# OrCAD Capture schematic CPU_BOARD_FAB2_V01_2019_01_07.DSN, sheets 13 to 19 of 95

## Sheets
13 054 COM-E_TYPE7_AB_2: size B
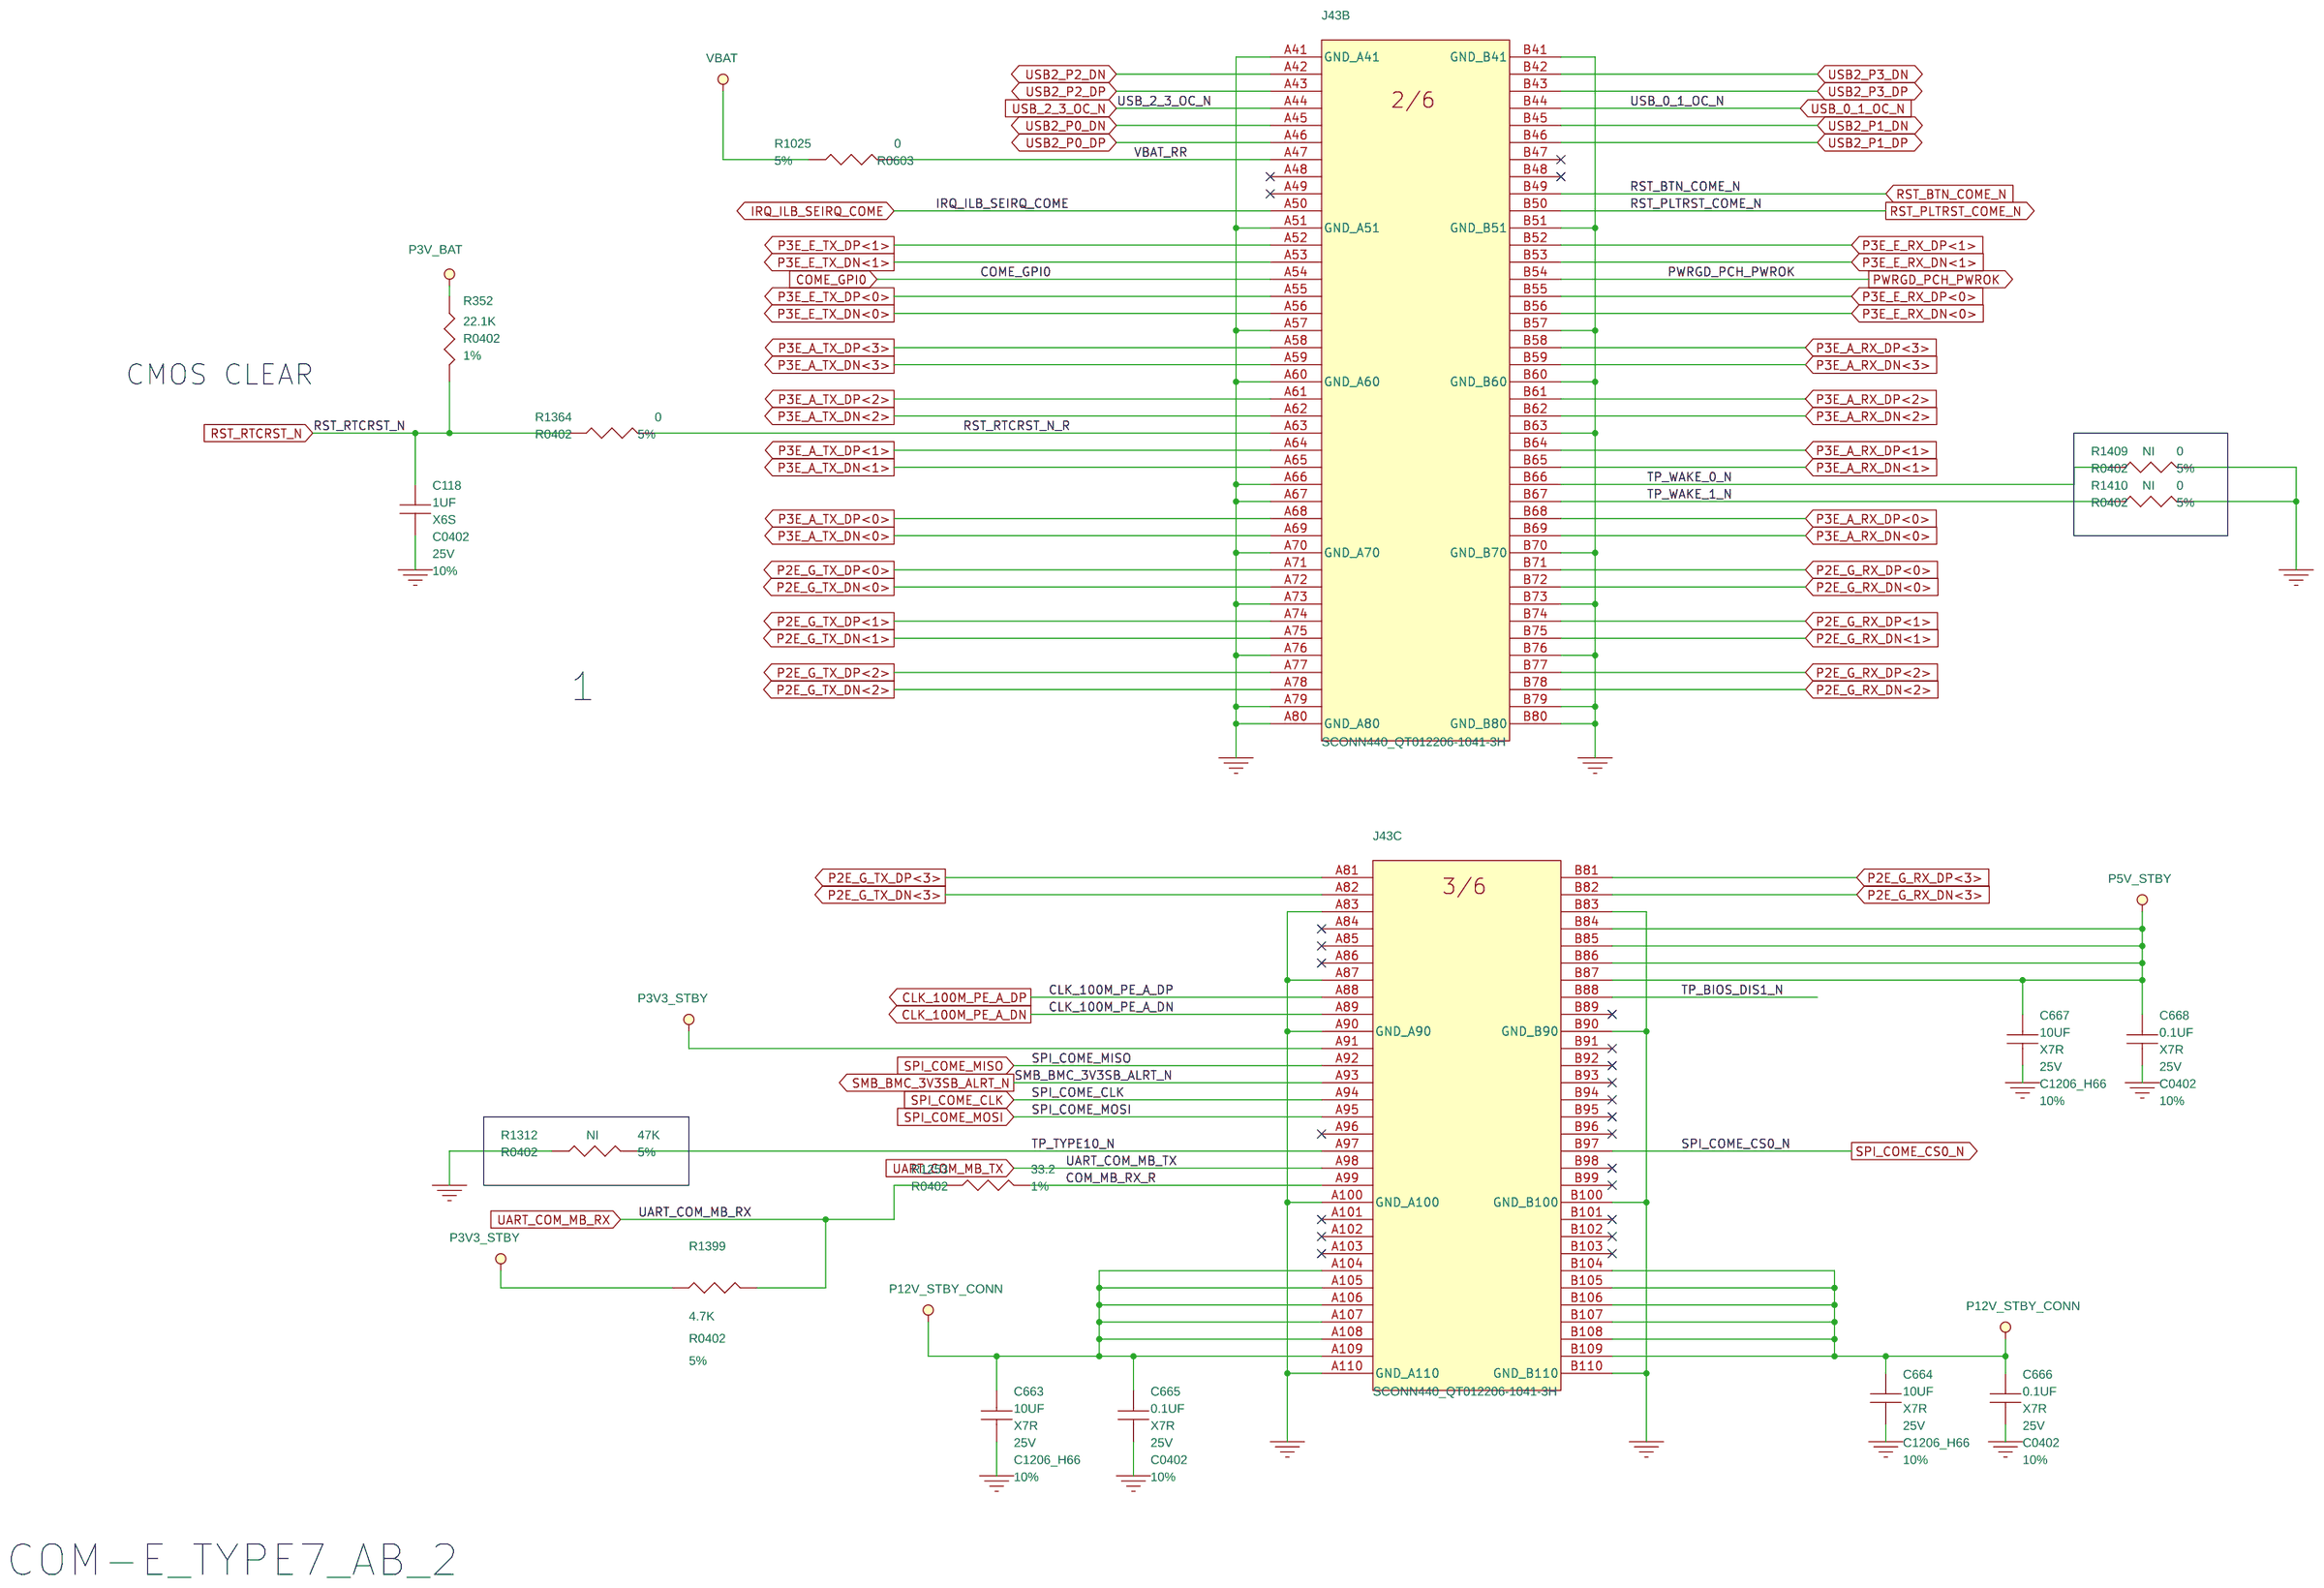
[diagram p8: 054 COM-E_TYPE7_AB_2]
14 052 CPLD_2: size B
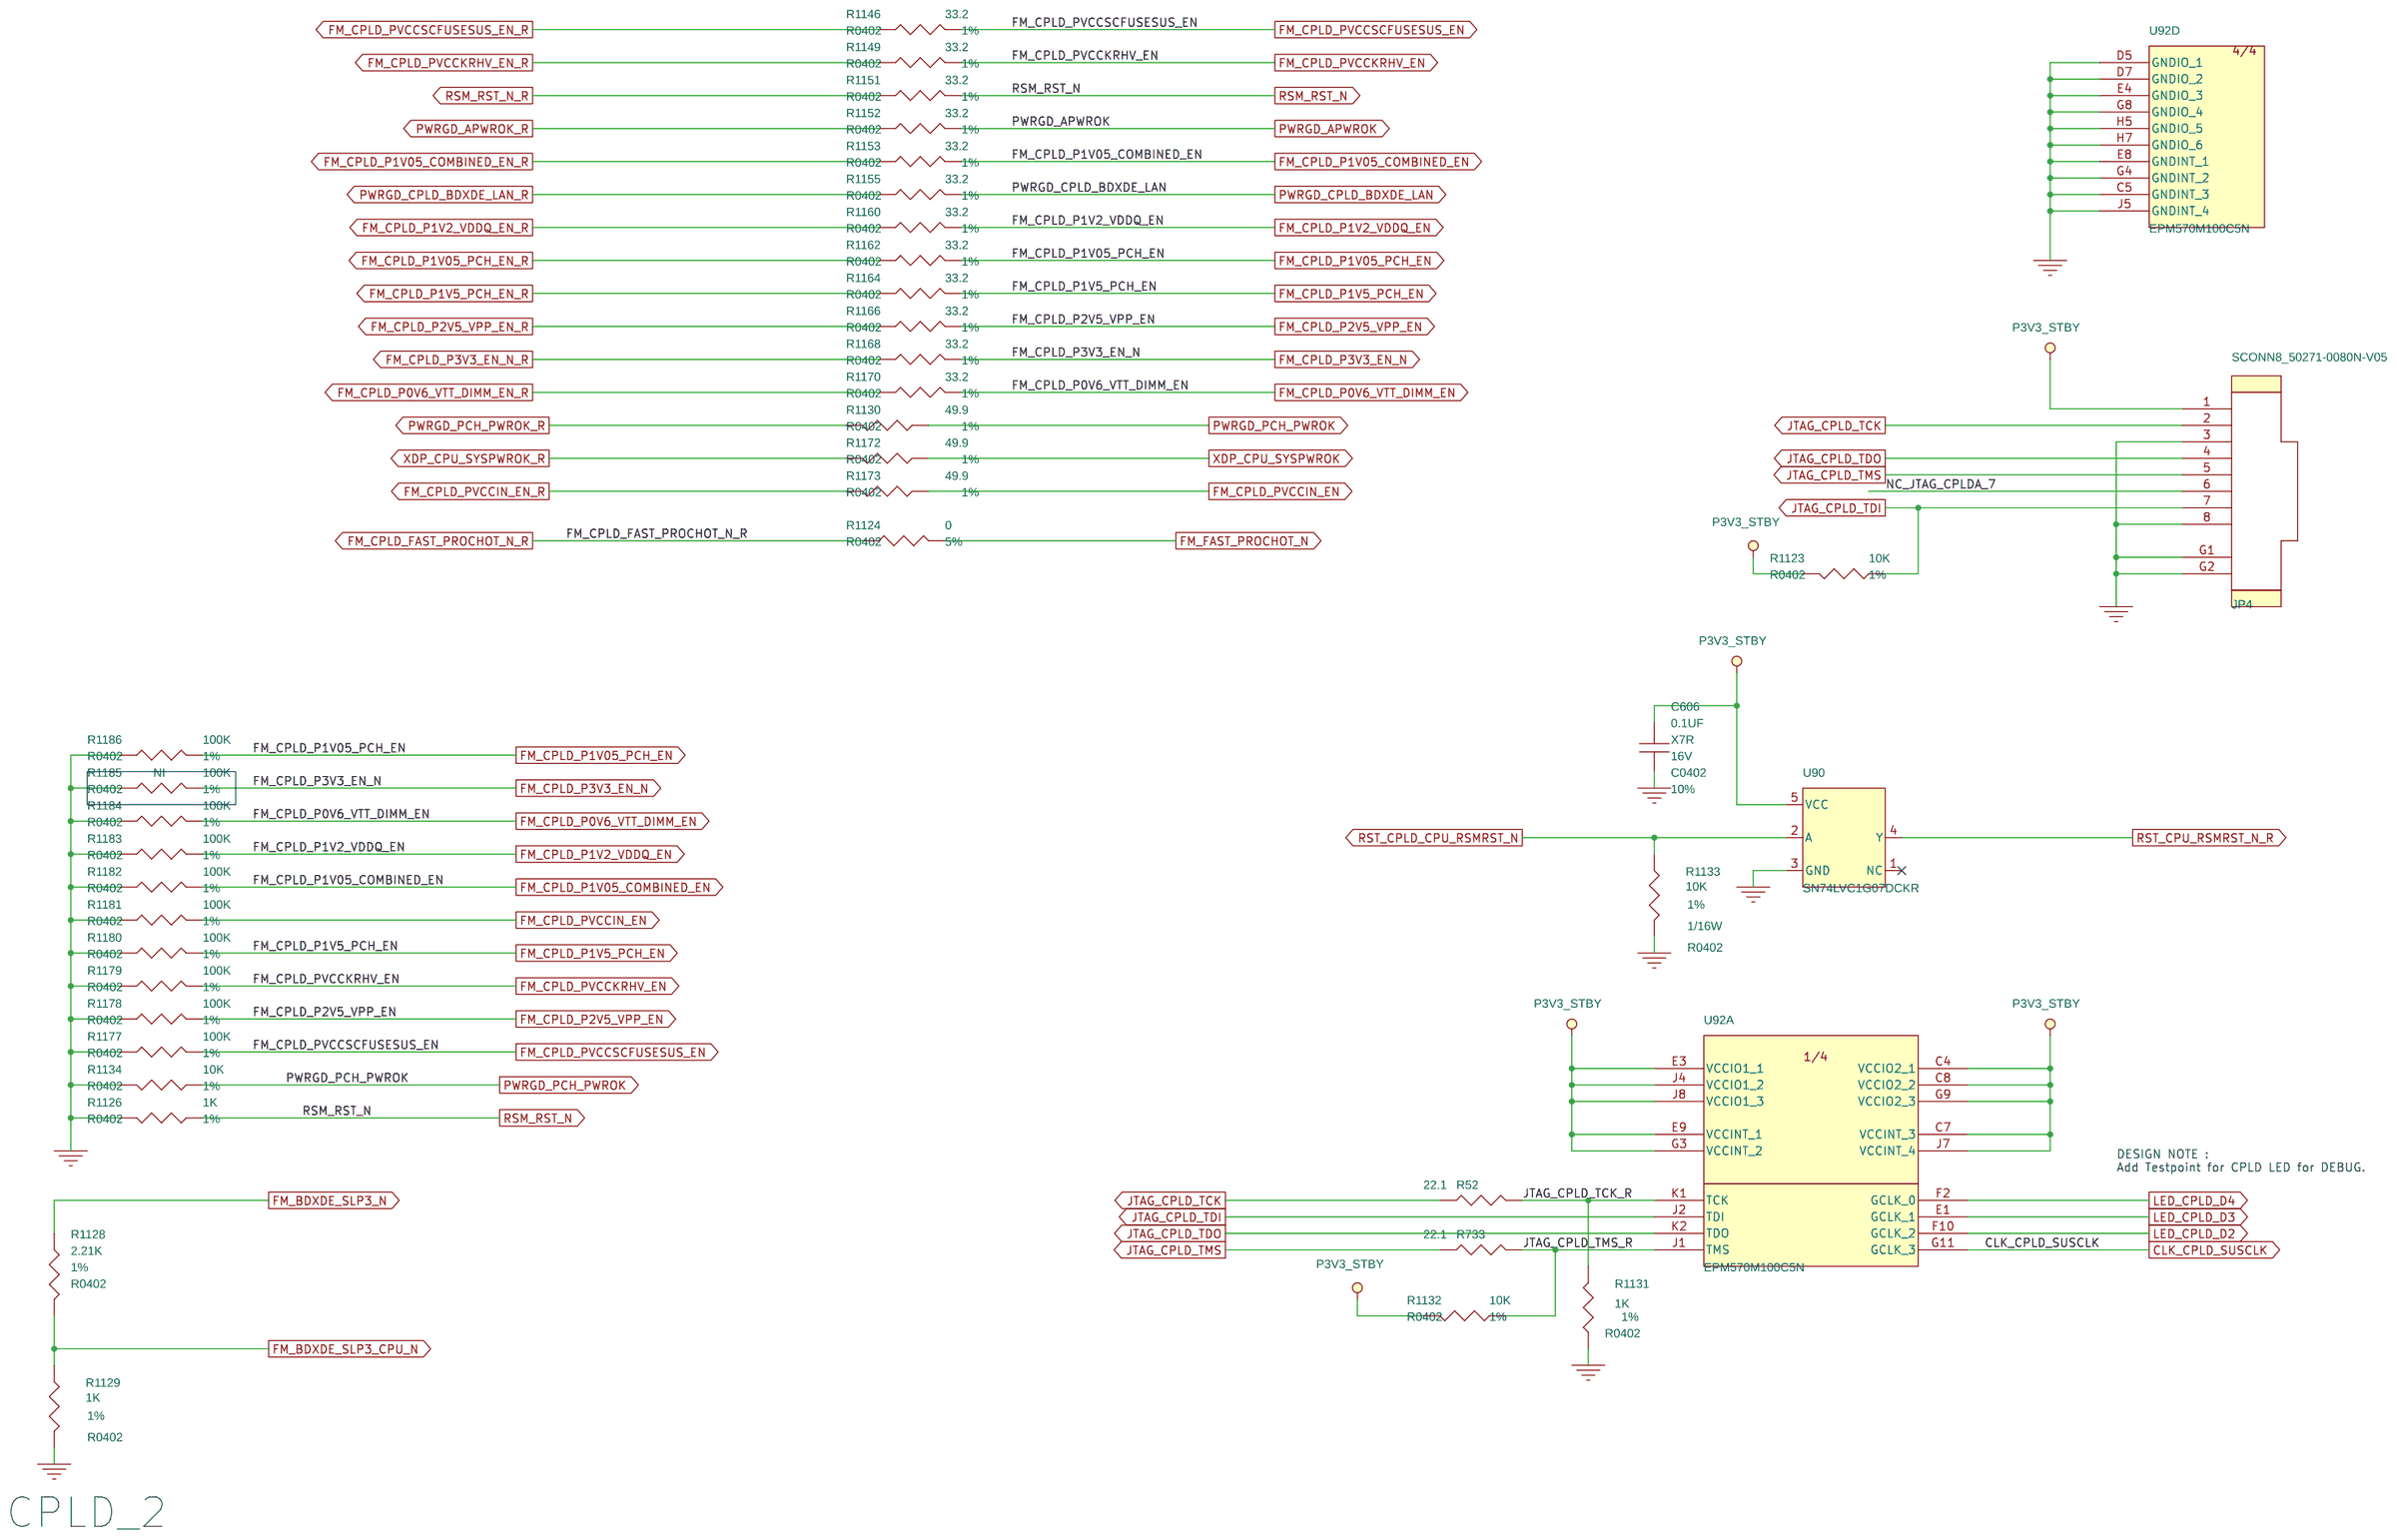
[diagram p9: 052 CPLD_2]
15 046 DDR4 SODIMM CHA_2: size B
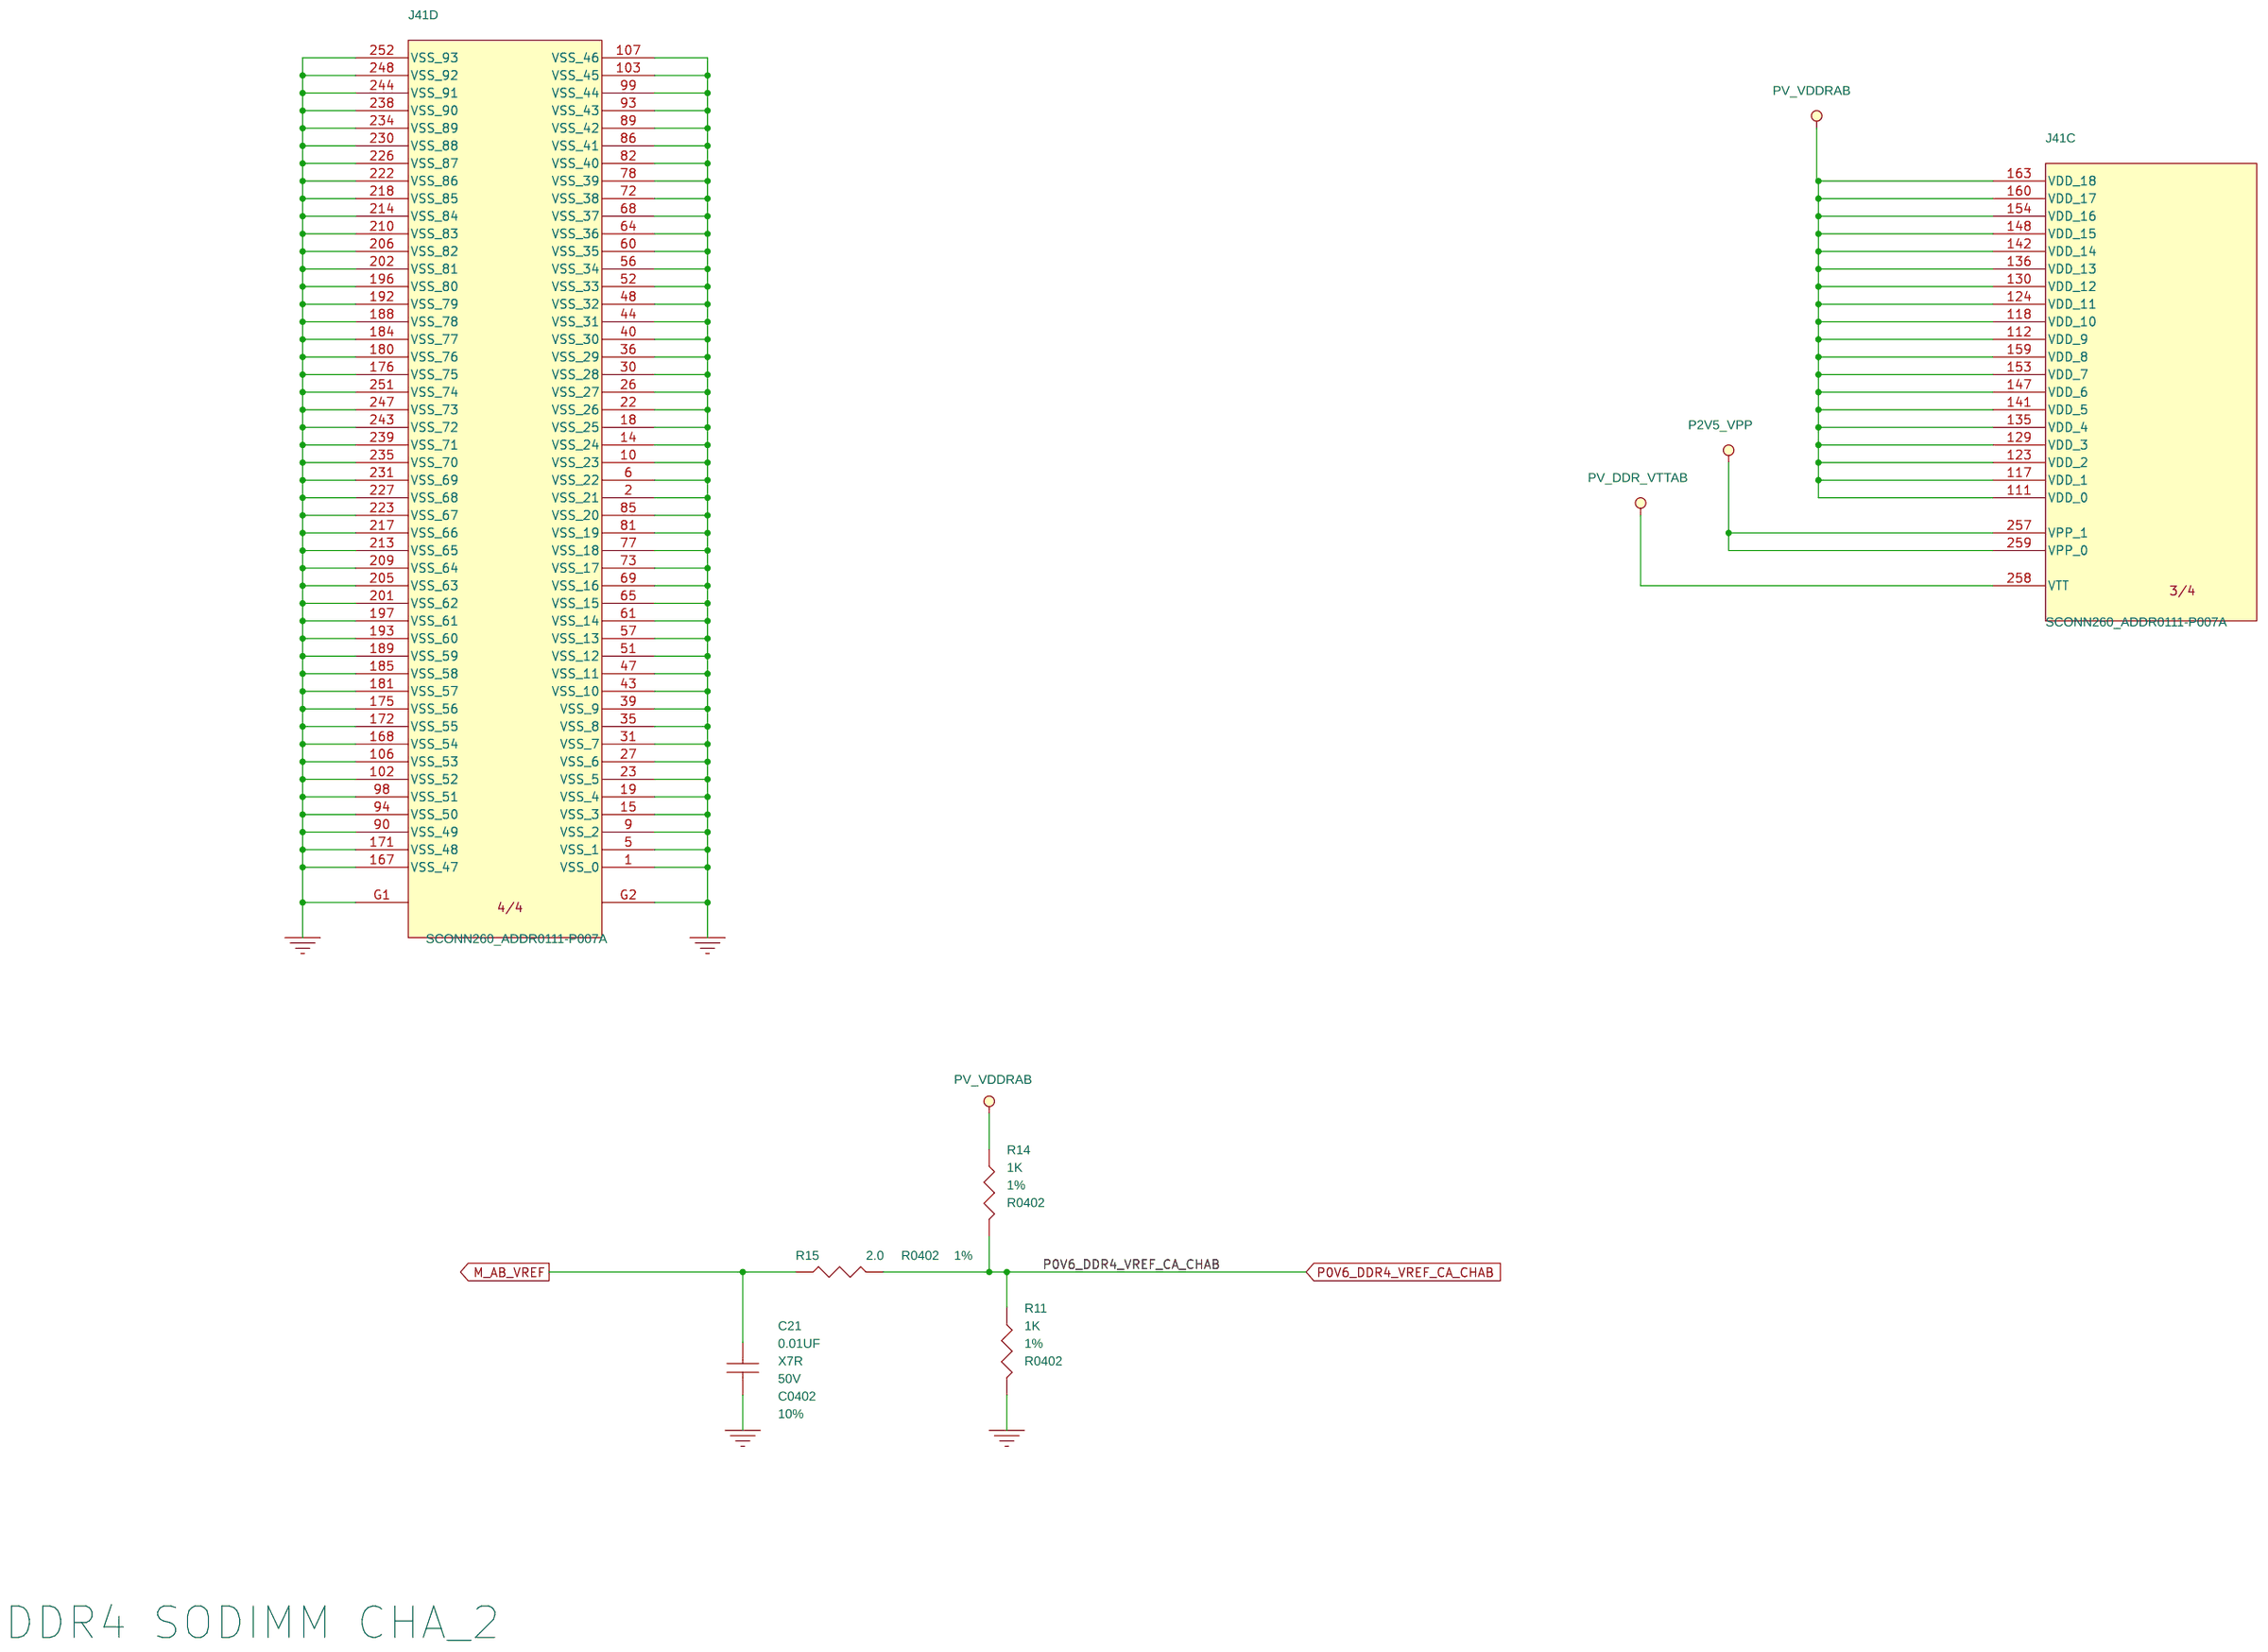
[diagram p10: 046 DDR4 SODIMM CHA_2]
16 037 CPU XDP_2: size B
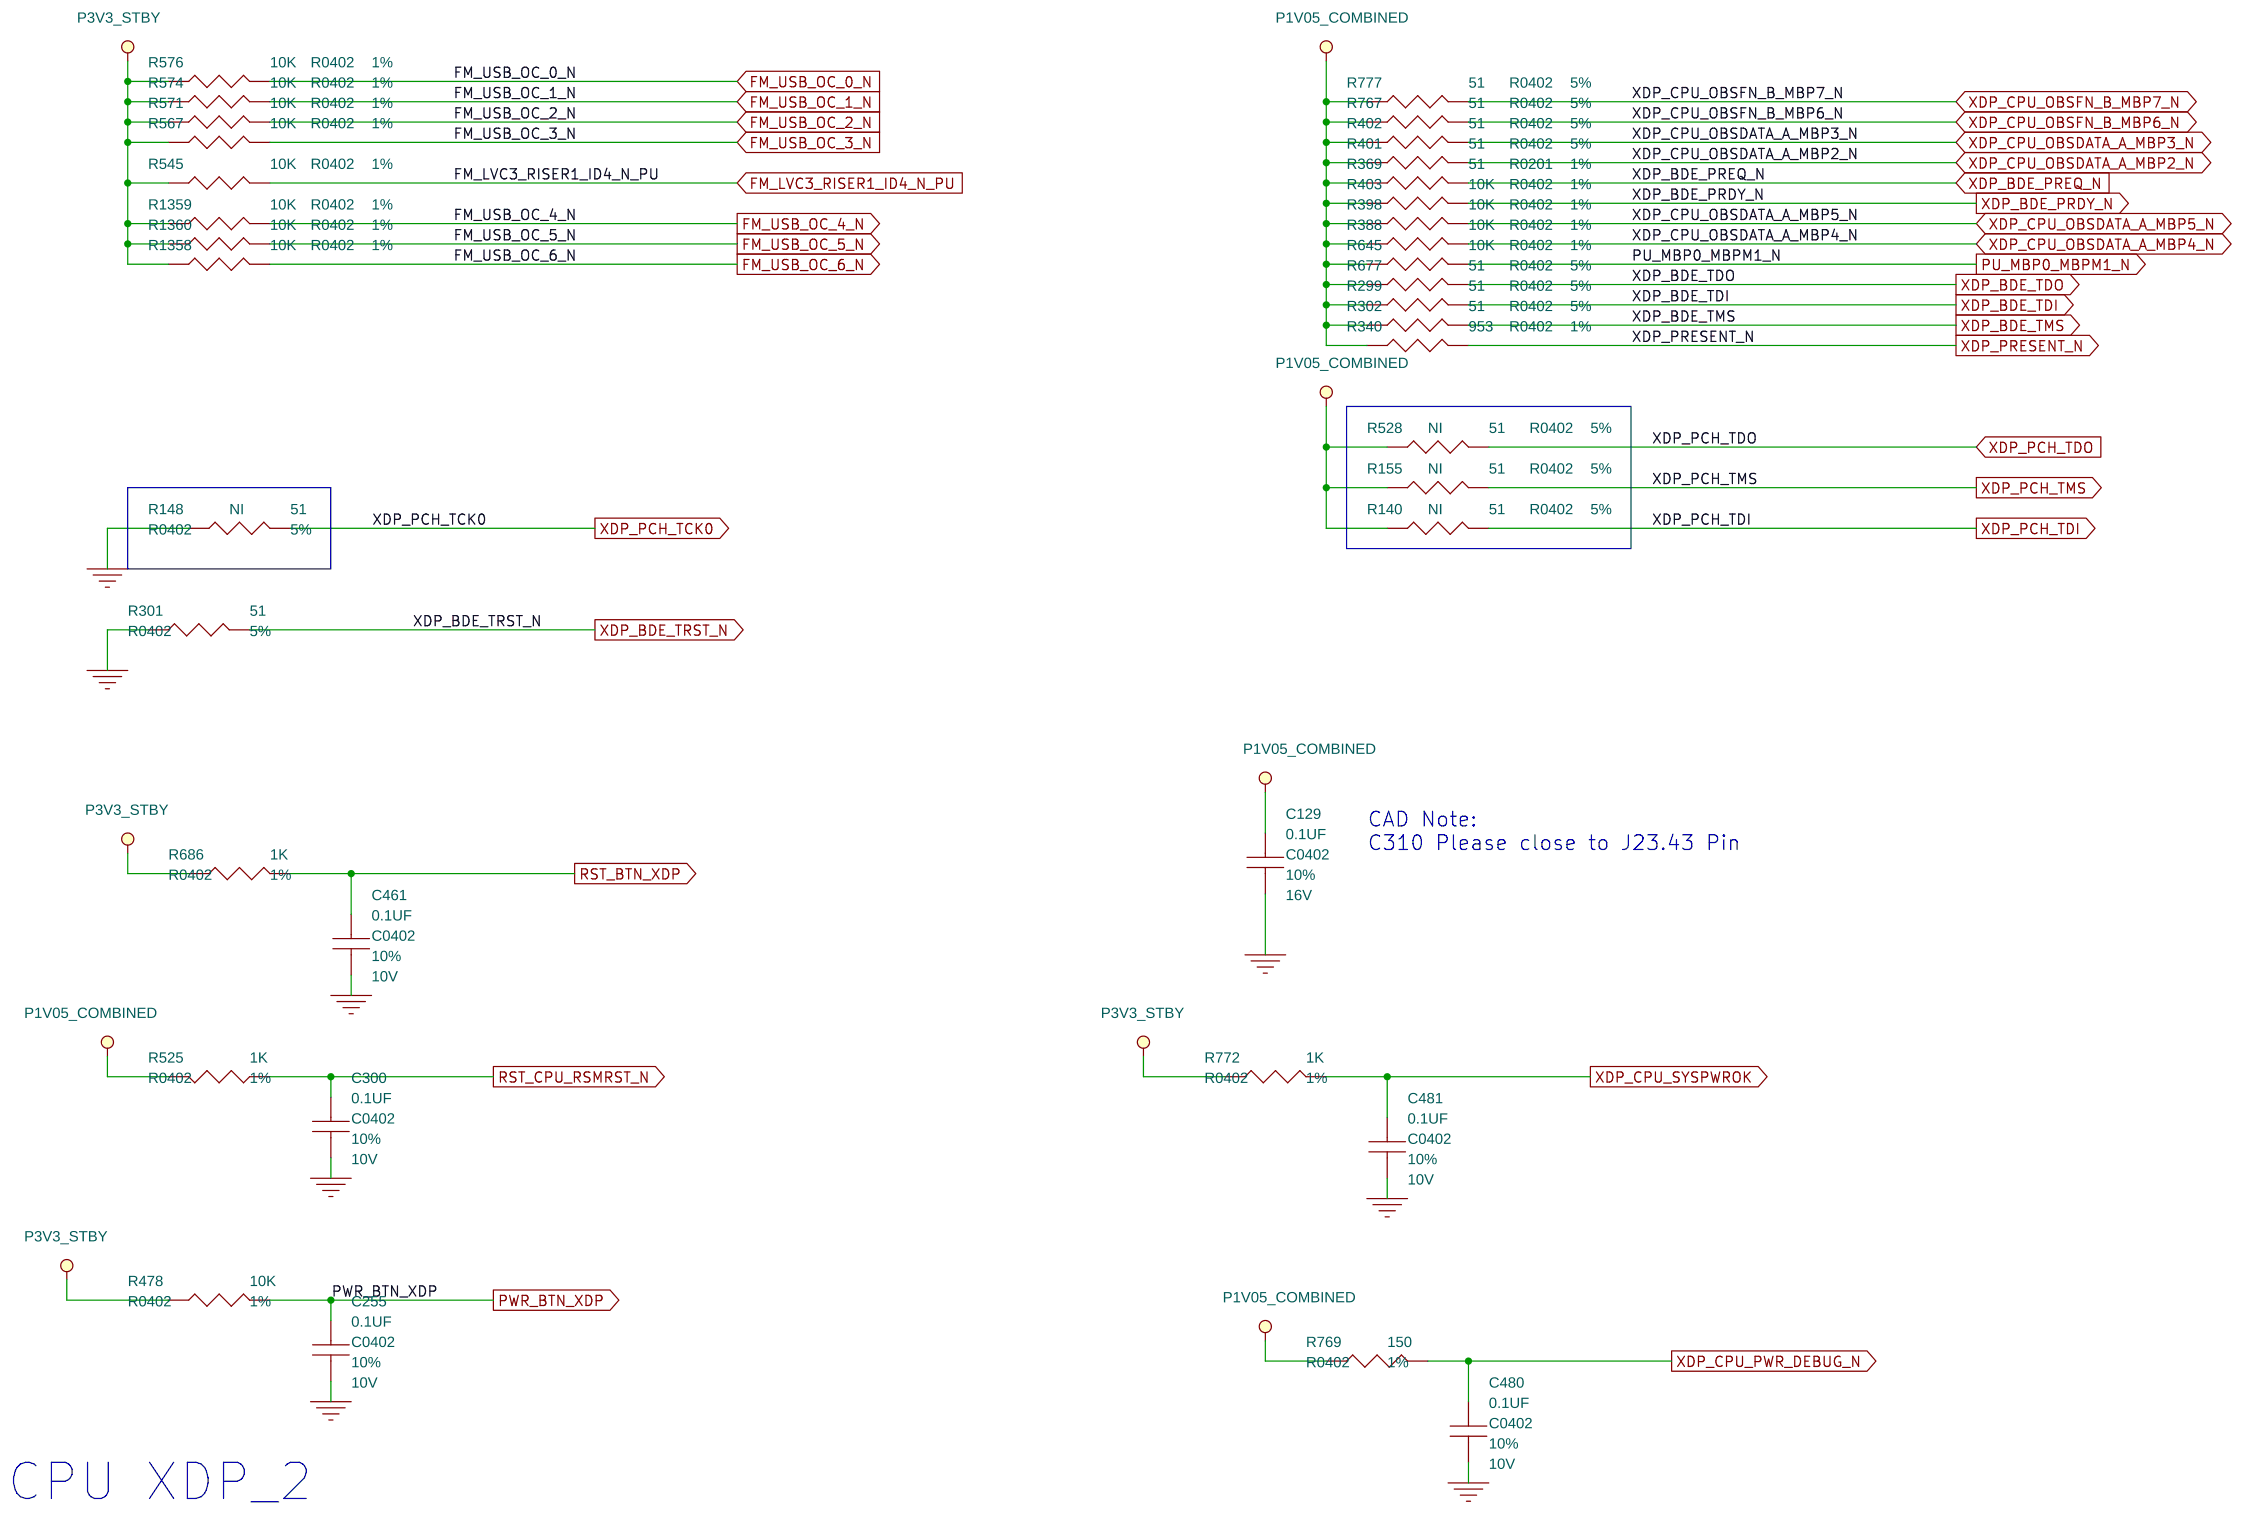
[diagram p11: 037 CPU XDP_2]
17 034 BDX-DE GND_2: size B
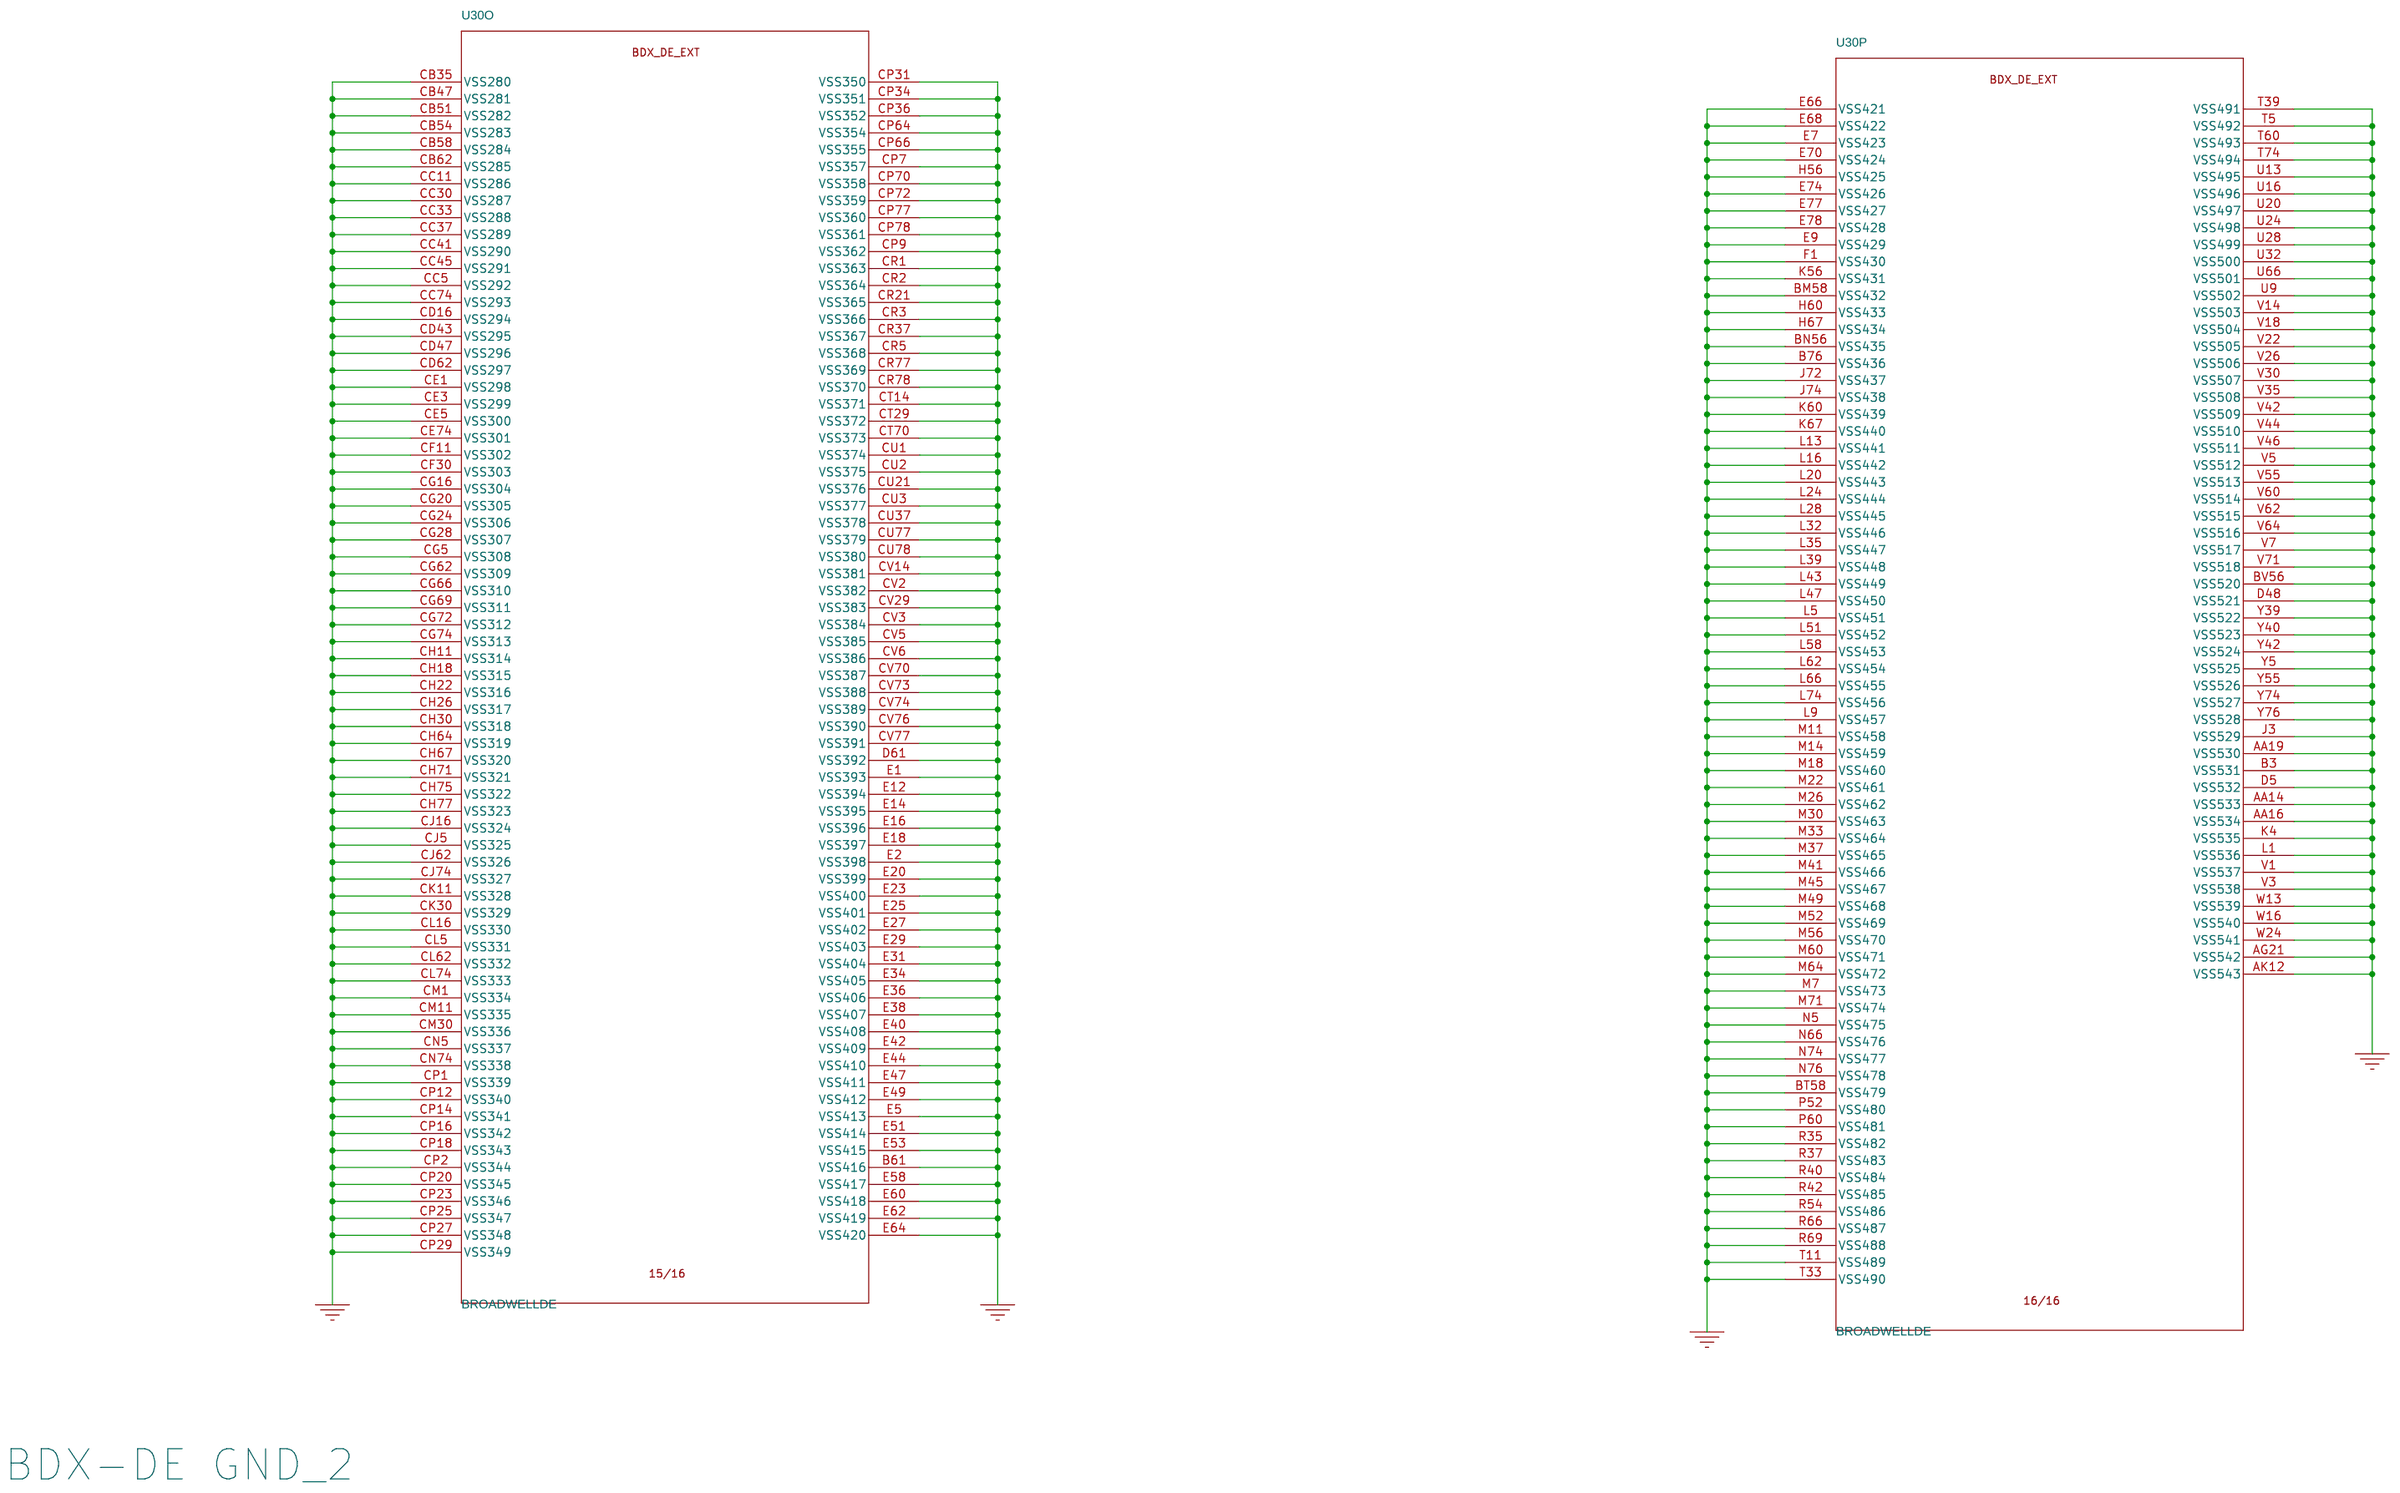
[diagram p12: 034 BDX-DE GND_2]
18 030 BDX-DE MISC,SMBUS: size B
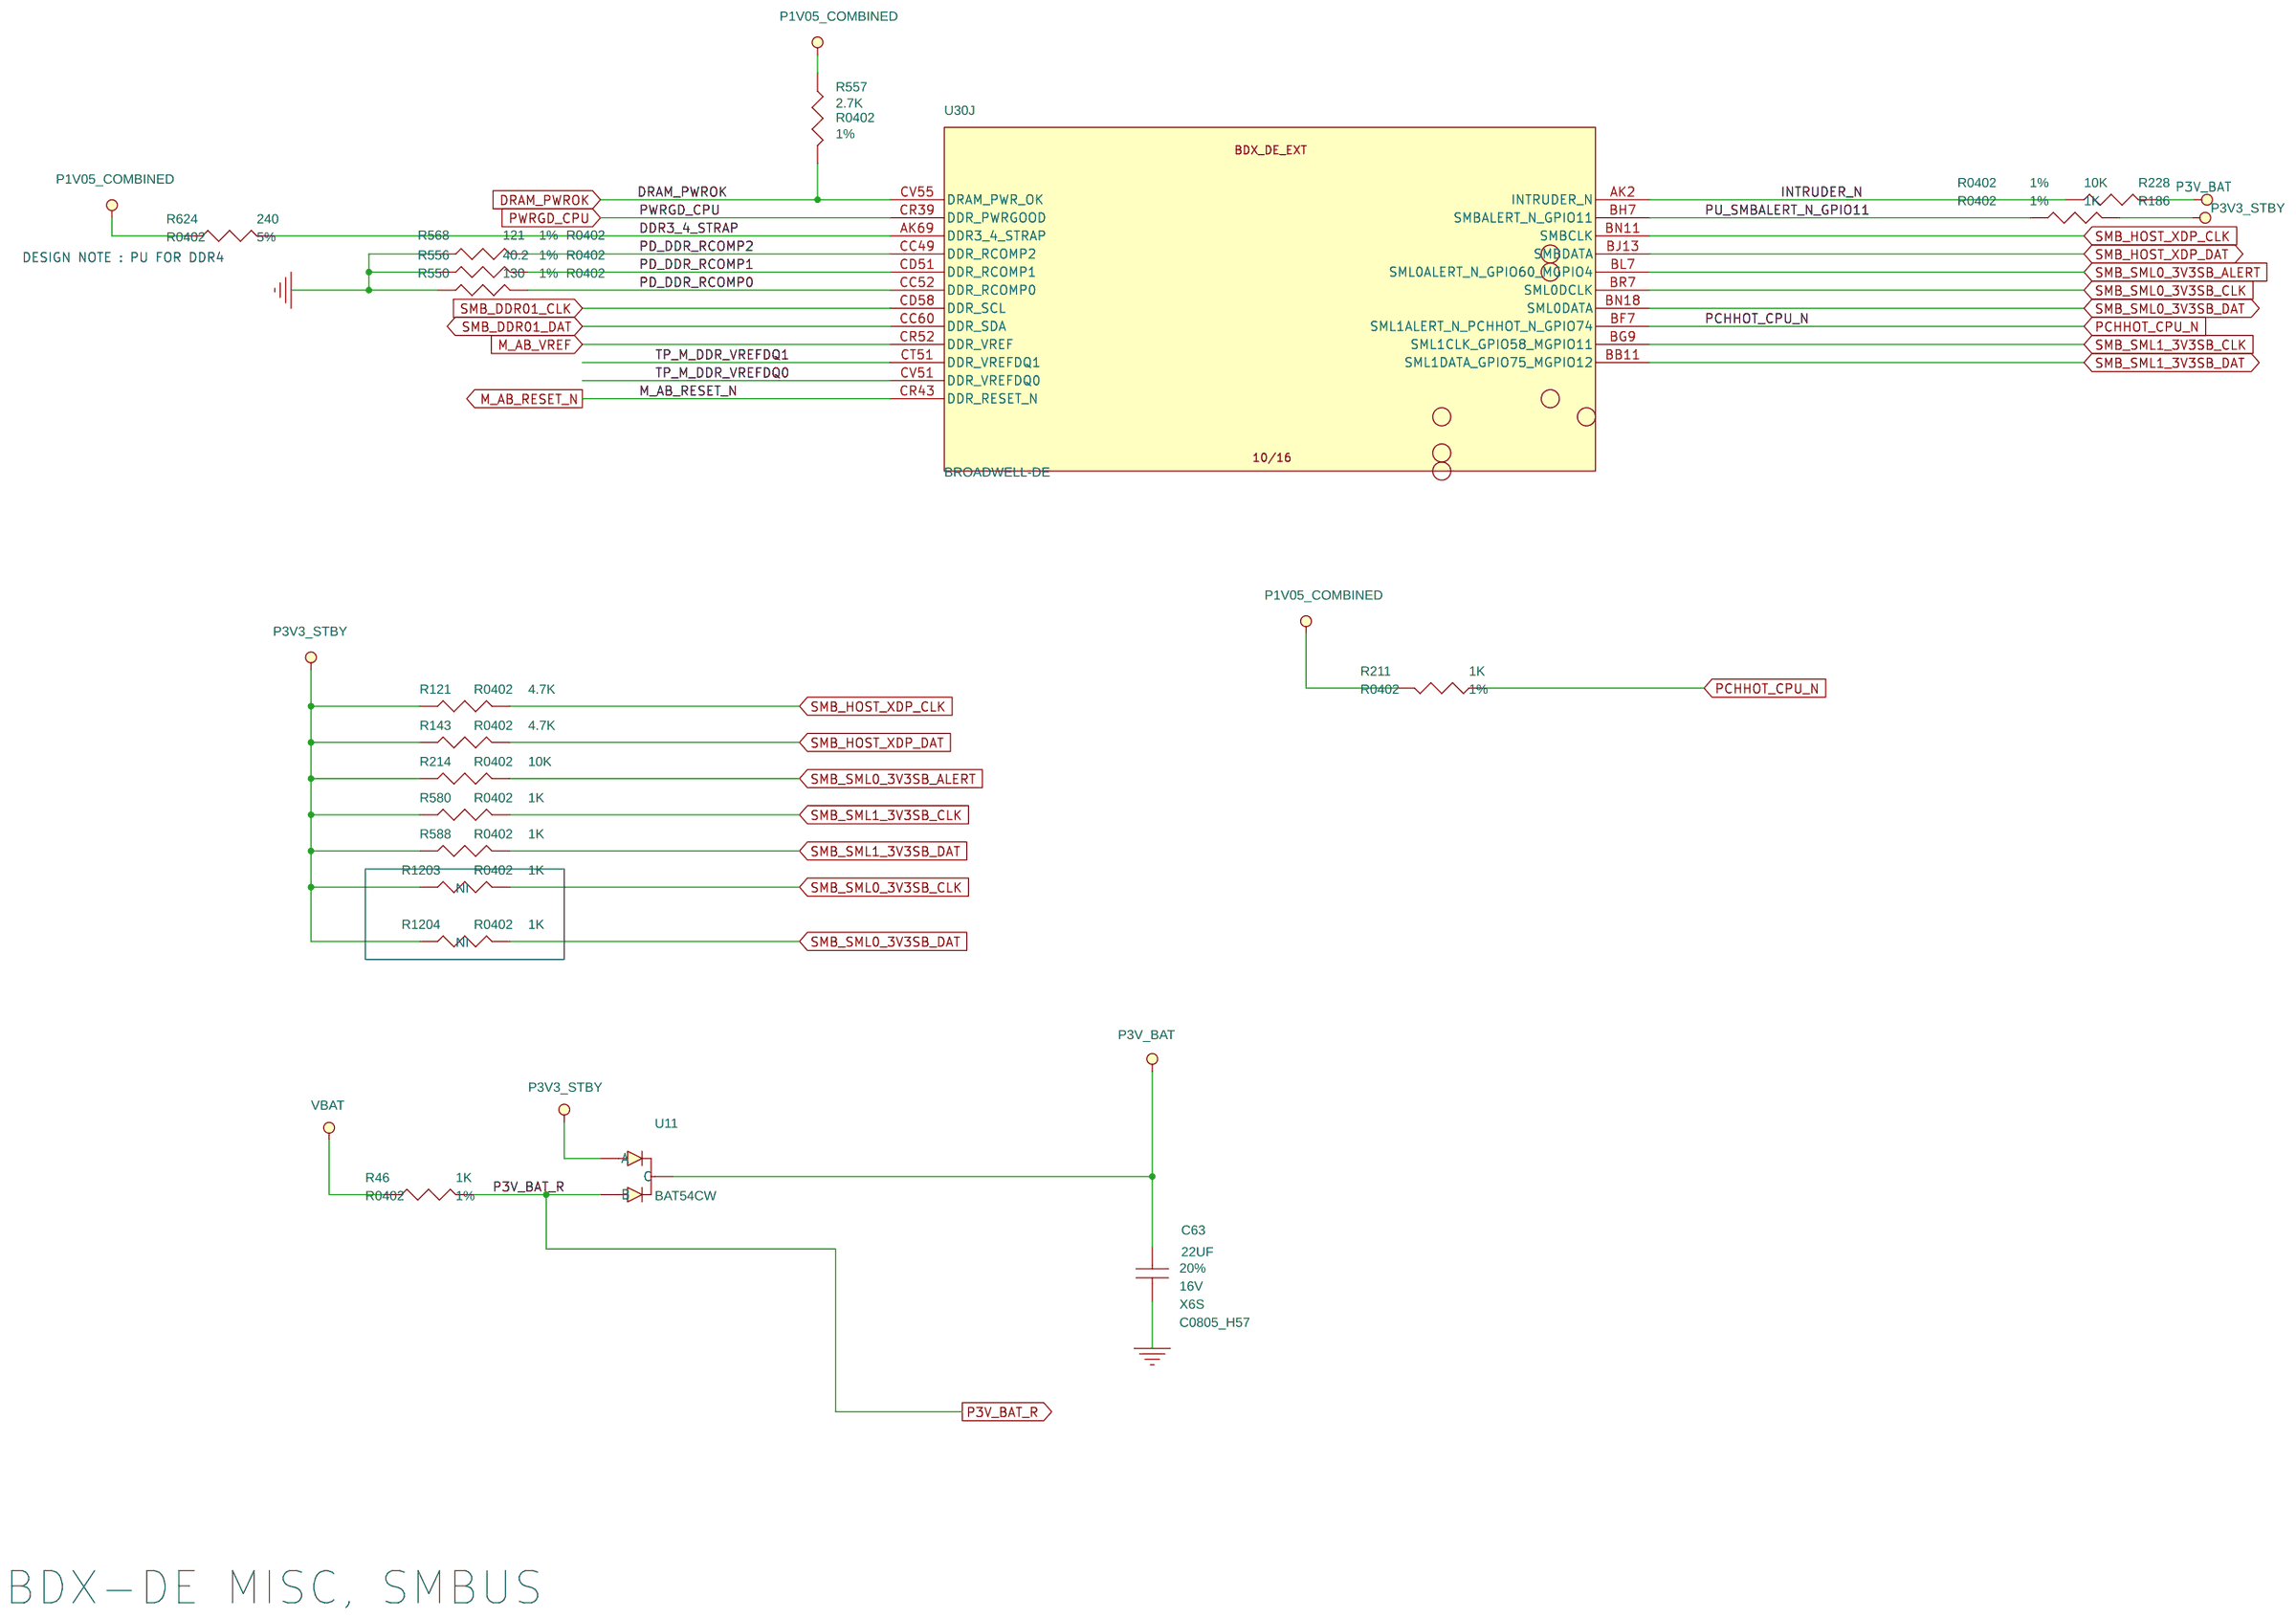
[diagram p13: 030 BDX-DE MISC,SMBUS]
19 027 BDX-DE UART,MGNT,INT,SVID_2: size B
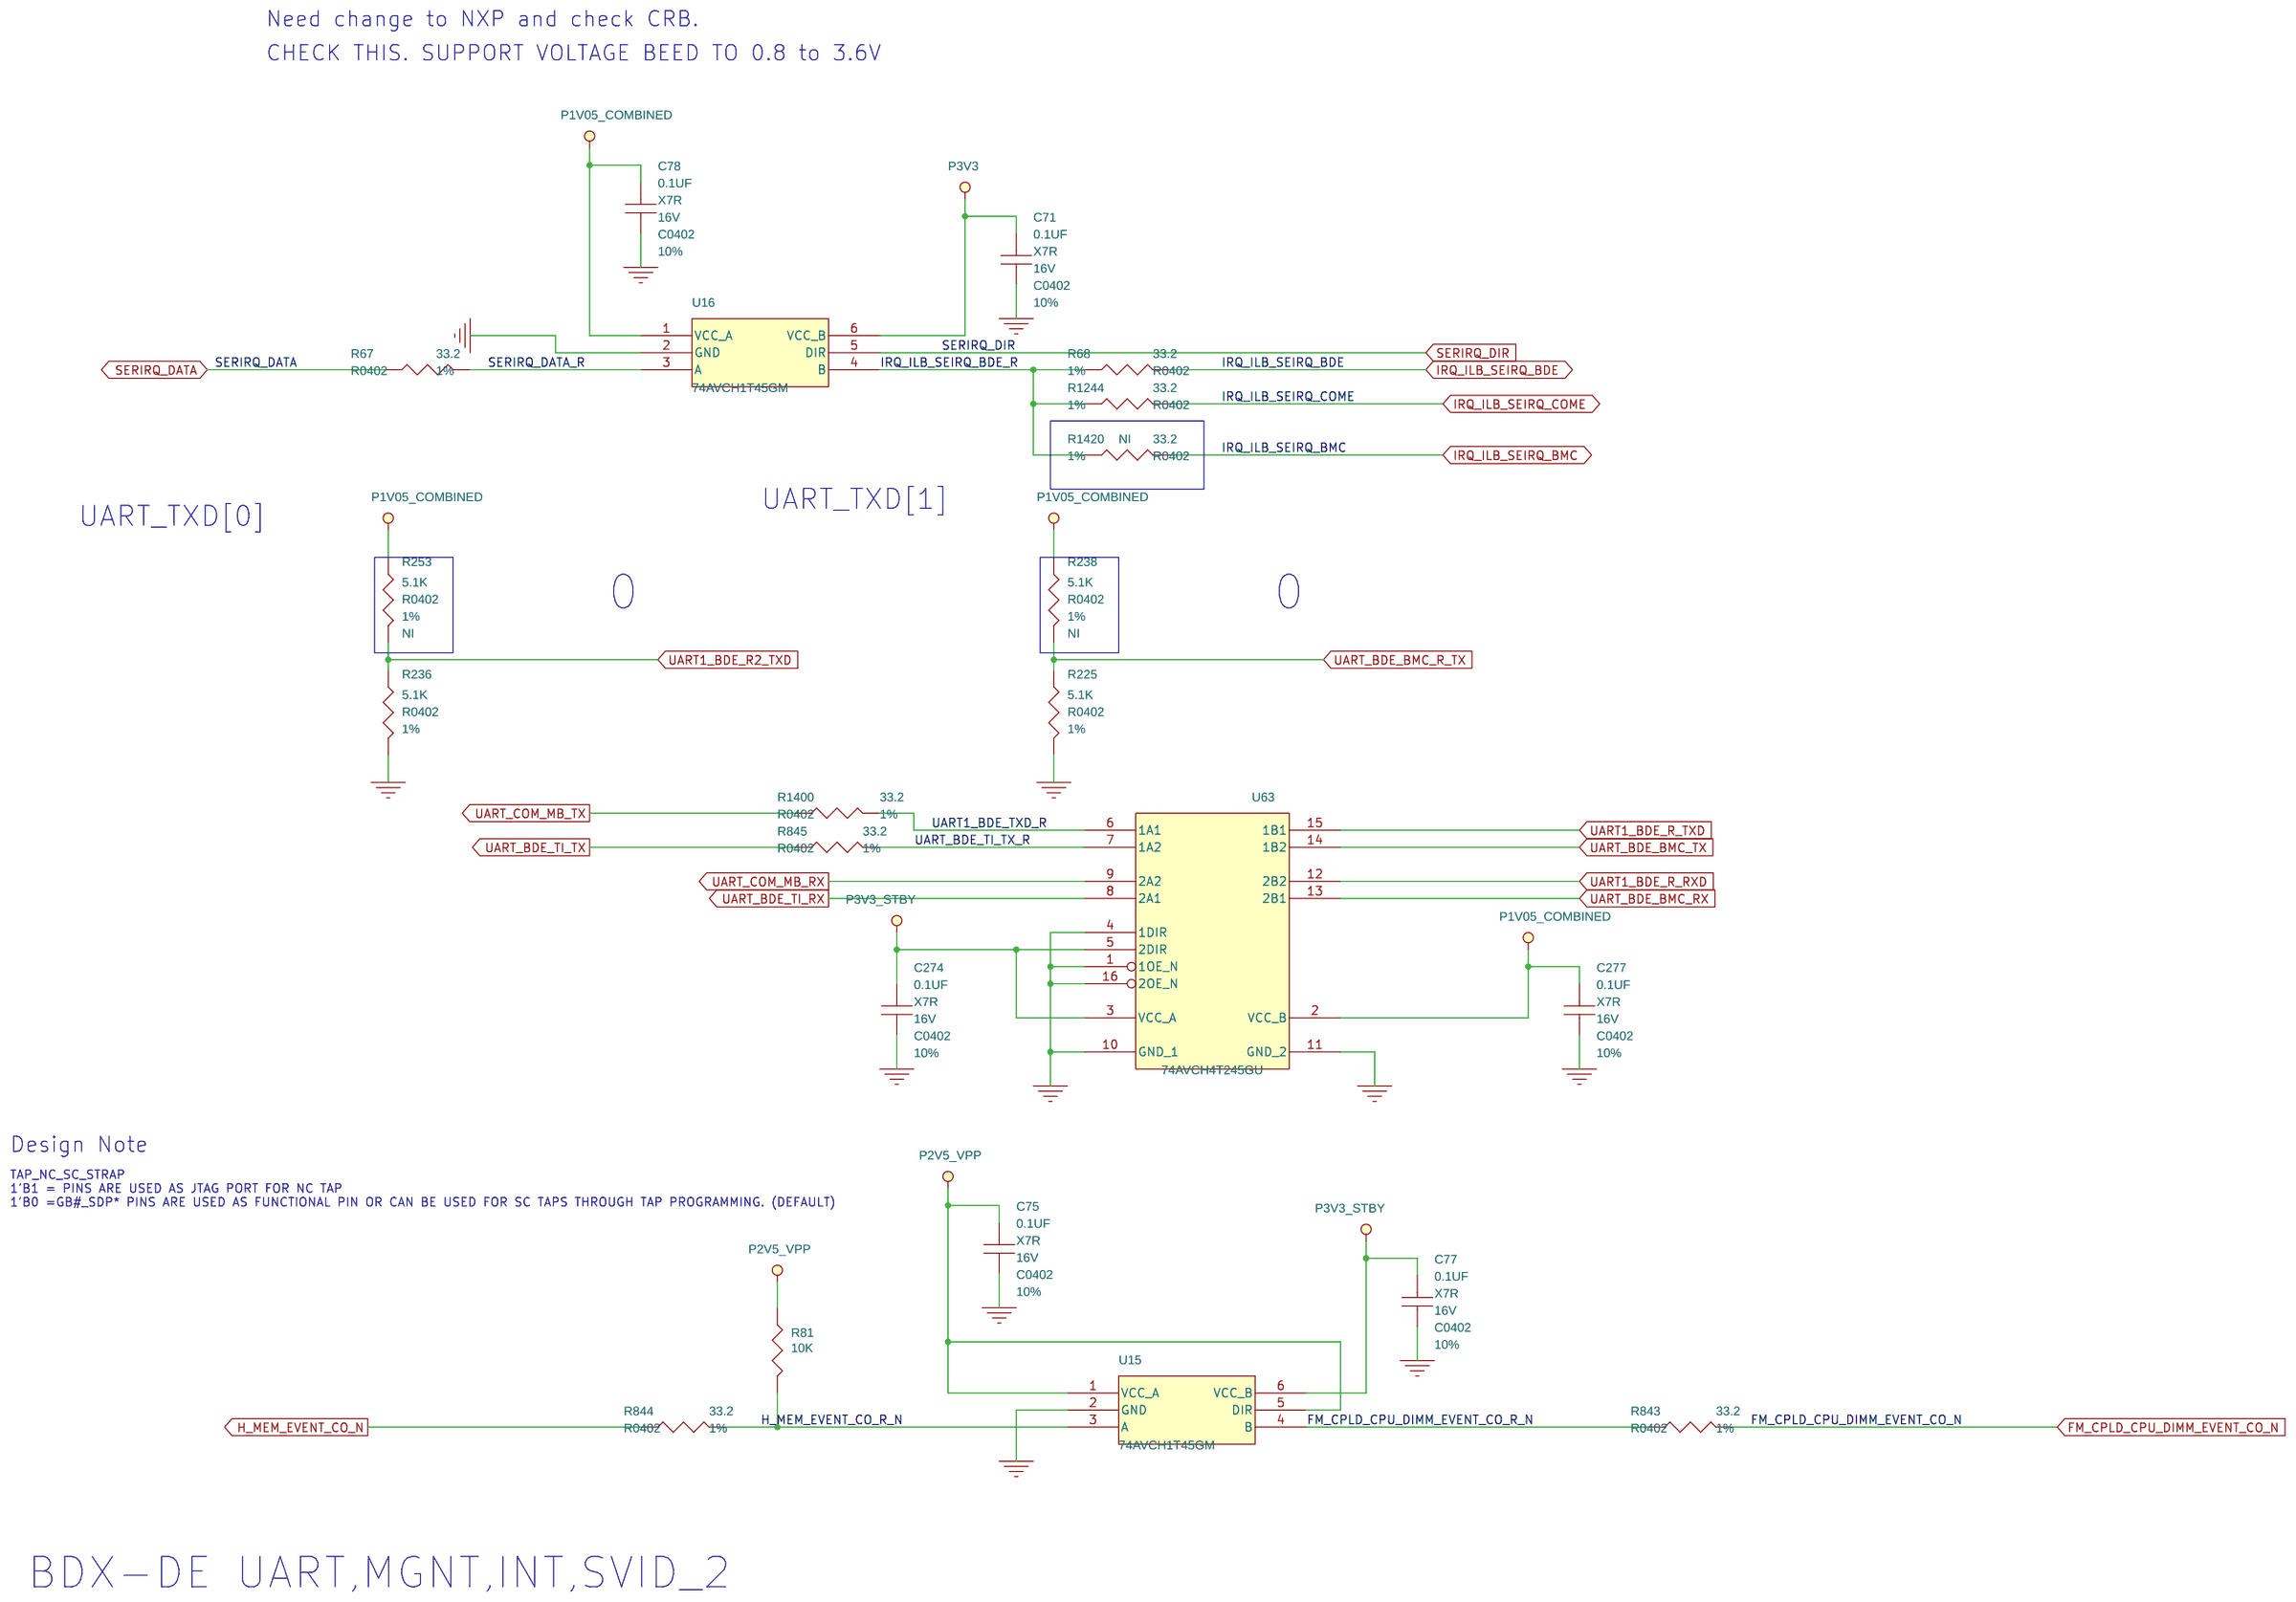
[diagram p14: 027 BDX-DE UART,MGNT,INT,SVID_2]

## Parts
sheet 023 BDX-DE SATA, USB2, USB3
U30  BROADWELL-DE  [BGA1667]  (sections A,B,C,D,E,F,G,H,I,J,K,L,M,N,O,P)
sheet 027 BDX-DE UART,MGNT,INT,SVID_2
C71  0.1UF  [C0402]
C75  0.1UF  [C0402]
C77  0.1UF  [C0402]
C78  0.1UF  [C0402]
C274  0.1UF  [C0402]
C277  0.1UF  [C0402]
R67  33.2  [R0402]
R68  33.2  [R0402]
R81  10K  [R0402]
R225  5.1K  [R0402]
R236  5.1K  [R0402]
R238  5.1K  [R0402]
R253  5.1K  [R0402]
R843  33.2  [R0402]
R844  33.2  [R0402]
R845  33.2  [R0402]
R1244  33.2  [R0402]
R1400  33.2  [R0402]
R1420  33.2  [R0402]
U15  74AVCH1T45GM  [SOT886]
U16  74AVCH1T45GM  [SOT886]
U63  74AVCH4T245GU  [XQFN16]
sheet 030 BDX-DE MISC,SMBUS
C63  22UF  [C0805_H57]
R46  1K  [R0402]
R121  4.7K  [R0402]
R143  4.7K  [R0402]
R186  1K  [R0402]
R211  1K  [R0402]
R214  10K  [R0402]
R228  10K  [R0402]
R550  130  [R0402]
R556  40.2  [R0402]
R557  2.7K  [R0402]
R568  121  [R0402]
R580  1K  [R0402]
R588  1K  [R0402]
R624  240  [R0402]
R1203  1K  [R0402]
R1204  1K  [R0402]
U11  BAT54CW  [SOT323]
sheet 037 CPU XDP_2
C129  0.1UF  [C0402]
C255  0.1UF  [C0402]
C300  0.1UF  [C0402]
C461  0.1UF  [C0402]
C480  0.1UF  [C0402]
C481  0.1UF  [C0402]
R140  51  [R0402]
R148  51  [R0402]
R155  51  [R0402]
R299  51  [R0402]
R301  51  [R0402]
R302  51  [R0402]
R340  953  [R0402]
R369  51  [R0201]
R388  10K  [R0402]
R398  10K  [R0402]
R401  51  [R0402]
R402  51  [R0402]
R403  10K  [R0402]
R478  10K  [R0402]
R525  1K  [R0402]
R528  51  [R0402]
R545  10K  [R0402]
R567  10K  [R0402]
R571  10K  [R0402]
R574  10K  [R0402]
R576  10K  [R0402]
R645  10K  [R0402]
R677  51  [R0402]
R686  1K  [R0402]
R767  51  [R0402]
R769  150  [R0402]
R772  1K  [R0402]
R777  51  [R0402]
R1358  10K  [R0402]
R1359  10K  [R0402]
R1360  10K  [R0402]
sheet 045 DDR4 SODIMM CHA_1
J41  SCONN260_ADDR0111-P007A  [SOCKET260S_RVSXH]  (sections A,B,C,D)
sheet 046 DDR4 SODIMM CHA_2
C21  0.01UF  [C0402]
R11  1K  [R0402]
R14  1K  [R0402]
R15  2.0  [R0402]
sheet 051 CPLD_1
U92  EPM570M100C5N  [BGA100XD_SMDC9_SM9]  (sections A,B,C,D)
sheet 052 CPLD_2
C606  0.1UF  [C0402]
JP4  SCONN8_50271-0080N-V05  [CON_8S1H2S_P1-25XE]
R52  22.1  [R0402]
R733  22.1  [R0402]
R1123  10K  [R0402]
R1124  0  [R0402]
R1126  1K  [R0402]
R1128  2.21K  [R0402]
R1129  1K  [R0402]
R1130  49.9  [R0402]
R1131  1K  [R0402]
R1132  10K  [R0402]
R1133  10K  [R0402]
R1134  10K  [R0402]
R1146  33.2  [R0402]
R1149  33.2  [R0402]
R1151  33.2  [R0402]
R1152  33.2  [R0402]
R1153  33.2  [R0402]
R1155  33.2  [R0402]
R1160  33.2  [R0402]
R1162  33.2  [R0402]
R1164  33.2  [R0402]
R1166  33.2  [R0402]
R1168  33.2  [R0402]
R1170  33.2  [R0402]
R1172  49.9  [R0402]
R1173  49.9  [R0402]
R1177  100K  [R0402]
R1178  100K  [R0402]
R1179  100K  [R0402]
R1180  100K  [R0402]
R1181  100K  [R0402]
R1182  100K  [R0402]
R1183  100K  [R0402]
R1184  100K  [R0402]
R1185  100K  [R0402]
R1186  100K  [R0402]
U90  SN74LVC1G07DCKR  [SC70-5XB]
sheet 054 COM-E_TYPE7_AB_2
C118  1UF  [C0402]
C663  10UF  [C1206_H66]
C664  10UF  [C1206_H66]
C665  0.1UF  [C0402]
C666  0.1UF  [C0402]
C667  10UF  [C1206_H66]
C668  0.1UF  [C0402]
R352  22.1K  [R0402]
R1025  0  [R0603]
R1253  33.2  [R0402]
R1312  47K  [R0402]
R1364  0  [R0402]
R1399  4.7K  [R0402]
R1409  0  [R0402]
R1410  0  [R0402]
sheet 055 COM-E_TYPE7_CD_1
J43  SCONN440_QT012206-1041-3H  [CON_440S4H4D4S_P0-5_LUH]  (sections A,B,C,D,E,F)

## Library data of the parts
U30 = BROADWELLDE: CPU(1667P)Broadwell-DE (FCBGA); CLASS: IC; Data: INT_Broadwell-DE_REV0_75.pdf; From_pj: S1M-MANSON; MATERIAL: IC; Manuf_name: INTEGRATED DEVICE TECHNOLOGY,INC.; Manuftr: INT; Part_Type: Tmp; Color: Default; Location X-Coordinate: 0; Location Y-Coordinate: 0; Power Pins Visible: False; Primitive: DEFAULT
C71 C75 C77 C78 C274 C277 C606 = CAP_NP: CAP CHIP 0.1U 16V(10%.X7R.0402); CLASS: DISCRETE; CMPLS_LVL: EP(V1); Data: MUR_LF_CAP SERIES_1.pdf; From_pj: S5A-TRAVIS; Lifecycle: Comp-Approve; MATERIAL: X7R; Manuf_PN: WBM155R71C104K; Manuf_name: MURATA ERIE N.A. INC TAIWAN BRANCH Okayama Murata Mfg.Co..Ltd. Wakura Murata Mfg; Manufacturer: MUR; Manuftr: MUR; Part_Type: *LF_C0402; RD_CMPLS_LVL: EP(V1); ROOM: VR_P1V05_PCH; TOLERANCE: 10%; Top_bot: TOP; VOLTAGE: 16V; fp_ECN: 0402 SERIES_LL34.xls
R67 R68 R843 R844 R1146 R1149 R1151-R1153 R1155 R1160 R1162 R1164 R1166 R1168 R1170 R1244 R1253 = R: RES CHIP 33.2 1/16W +-1%(0402); CLASS: DISCRETE; CMPLS_LVL: EP; Data: CYN_LF_RL SERIES.pdf; From_pj: A06-EDISON; Lifecycle: Comp-Approve; MATERIAL: CHIP; Manuf_PN: RR0510S-33R2-FN; Manuf_name: CYNTEC CO.. LTD.; Manuftr: CYN; Part_Type: *LF_Resistor; TOLERANCE: 1%; WATTAGE: 1/16W; fp_ECN: 0402 SERIES_LL34.xls
R81 R214 R228 R388 R398 R403 R478 R545 R567 R571 R574 R576 R645 R1123 R1132-R1134 R1358-R1360 = R: RES CHIP 10K 1/16W +-1% (0402); CLASS: DISCRETE; CMPLS_LVL: EP; Data: WTC_LF_WR SERIES.pdf; From_pj: S82; Lifecycle: Comp-Approve; MATERIAL: CHIP; Manuf_PN: RR0510S-103-FN; Manuf_name: CYNTEC CO.. LTD.; Manuftr: CYN; Part_Type: *LF_Resistor; Status: Preferred; TOLERANCE: 1%; WATTAGE: 1/16W; fp_ECN: 0402 SERIES_LL34.xls
R225 R236 = R: RES CHIP 5.1K 1/16W +-1%(0402); CLASS: DISCRETE; CMPLS_LVL: EP; Data: MAT_LF_RES SERIES.pdf; From_pj: S10-ANTONY; Lifecycle: Comp-Approve; MATERIAL: CHIP; Manuf_PN: RR0510S-512-FN; Manuf_name: CYNTEC CO.. LTD.; Manuftr: CYN; Part_Type: *LF_Resistor; Status: Normal; TOLERANCE: 1%; WATTAGE: 1/16W; fp_ECN: 0402 SERIES_LL34.xls
R238 R253 = R: RES CHIP 5.1K 1/16W +-1%(0402); CLASS: DISCRETE; CMPLS_LVL: EP; Data: MAT_LF_RES SERIES.pdf; From_pj: S10-ANTONY; Lifecycle: Comp-Approve; MATERIAL: CHIP; Manuf_PN: RR0510S-512-FN; Manuf_name: CYNTEC CO.. LTD.; Manuftr: CYN; Not_insert: NI; Part_Type: *LF_Resistor; Status: Normal; TOLERANCE: 1%; WATTAGE: 1/16W; fp_ECN: 0402 SERIES_LL34.xls
R845 R1400 = R: RES CHIP 33.2 1/16W +-1%(0402); CLASS: DISCRETE; CMPLS_LVL: EP; Data: CYN_LF_RL SERIES.pdf; From_pj: A06-EDISON; Lifecycle: Comp-Approve; MATERIAL: CHIP; Manuf_PN: RR0510S-33R2-FN; Manuf_name: CYNTEC CO.. LTD.; Manufacturer: CYN; Manuftr: CYN; Part_Type: *LF_Resistor; TOLERANCE: 1%; WATTAGE: 1/16W; fp_ECN: 0402 SERIES_LL34.xls; top_bot: TOP
R1420 = R: RES CHIP 33.2 1/16W +-1%(0402); CLASS: DISCRETE; CMPLS_LVL: EP; Data: CYN_LF_RL SERIES.pdf; From_pj: A06-EDISON; Lifecycle: Comp-Approve; MATERIAL: CHIP; Manuf_PN: RR0510S-33R2-FN; Manuf_name: CYNTEC CO.. LTD.; Manuftr: CYN; Not_insert: NI; Part_Type: *LF_Resistor; TOLERANCE: 1%; WATTAGE: 1/16W; fp_ECN: 0402 SERIES_LL34.xls
U15 U16 = 74AVCH1T45GM: IC OTHER(6P) 74AVCH1T45GM(XSON); CLASS: IC; CMPLS_LVL: EP(V1); Data: NXP_74AVCH1T45GM_REV4.pdf; From_pj: F07-HENRY; Lifecycle: Comp-Approve; MATERIAL: IC; Manuf_name: NXP semiconductors; Manuftr: NXP; Part_Type: *LF_Chipset; RD_CMPLS_LVL: EP(V1); Standard: Potential
U63 = 74AVCH4T245GU: IC OTHER(16P) 74AVCH4T245GU(XQFN); CLASS: IC; CMPLS_LVL: EP(V1); Data: NXP_74AVCH4T245GU_REV4.pdf; From_pj: F07-HENRY; Lifecycle: Comp-Approve; MATERIAL: IC; Manuf_name: NXP semiconductors; Manuftr: NXP; Part_Type: *LF_Chipset; RD_CMPLS_LVL: EP(V1); Standard: Potential
C63 = CAP_NP: CAP CHIP 22U 16V(+-20%,X6S,0805); CLASS: DISCRETE; Data: MUR_GRM21BC81C226ME44L.pdf; From_pj: F08-ATLUS; Lifecycle: Comp-Approve; MATERIAL: X6S; Manuf_PN: GRM21BC81C226M; Manuf_name: MURATA ERIE N.A. INC TAIWAN BRANCH Okayama Murata Mfg.Co.,Ltd.Wakura Murata Mfg.; Manuftr: MUR; Part_Type: *LF_C0805; RD_CMPLS_LVL: EP(V1); TOLERANCE: 20%; VOLTAGE: 16V
R46 = R: RES CHIP 1K 1/16W +-1% (0402); CLASS: DISCRETE; CMPLS_LVL: EP; Data: WTC_LF_WR SERIES.pdf; Lifecycle: Comp-Approve; MATERIAL: CHIP; Manuf_PN: RR0510S-102-FN; Manuf_name: CYNTEC CO.. LTD.; Manufacturer: CYN; Manuftr: CYN; Part_Type: *LF_Resistor; Status: Preferred; TOLERANCE: 1%; WATTAGE: 1/16W; fp_ECN: 0402 SERIES_LL34.xls
R121 R143 R1399 = R: RES CHIP 4.7K 1/16W +-5% (0402); CLASS: DISCRETE; CMPLS_LVL: EP; Data: WTC_LF_WR SERIES.pdf; Lifecycle: Comp-Approve; MATERIAL: CHIP; Manuf_PN: RR0510S-472-JN; Manuf_name: CYNTEC CO.. LTD.; Manuftr: CYN; Part_Type: *LF_Resistor; Status: Preferred; TOLERANCE: 5%; WATTAGE: 1/16W; fp_ECN: 0402 SERIES_LL34.xls
R11 R14 R186 R211 R525 R580 R588 R686 R772 R1126 R1129 R1131 = R: RES CHIP 1K 1/16W +-1% (0402); CLASS: DISCRETE; CMPLS_LVL: EP; Data: WTC_LF_WR SERIES.pdf; Lifecycle: Comp-Approve; MATERIAL: CHIP; Manuf_PN: RR0510S-102-FN; Manuf_name: CYNTEC CO.. LTD.; Manuftr: CYN; Part_Type: *LF_Resistor; Status: Preferred; TOLERANCE: 1%; WATTAGE: 1/16W; fp_ECN: 0402 SERIES_LL34.xls
R550 = R: RES CHIP 130 1/16W +-1%(0402)L-F; CLASS: DISCRETE; CMPLS_LVL: EP; Data: CYN_LF_RL SERIES.pdf; From_pj: S99-JOSEPH; Lifecycle: Comp-Approve; MATERIAL: CHIP; Manuf_PN: RR0510S-131-FN; Manuf_name: CYNTEC CO.. LTD.; Manuftr: CYN; Part_Type: *LF_Resistor; TOLERANCE: 1%; WATTAGE: 1/16W; fp_ECN: 0402 SERIES_LL34.xls
R556 = R: RES CHIP 40.2 1/16W +-1%(0402); CLASS: DISCRETE; CMPLS_LVL: EP(V1); Data: WTC_LF_WR SERIES.pdf; Lifecycle: Comp-Approve; MATERIAL: CHIP; Manuf_PN: RR0510S-40R2-FN; Manuf_name: CYNTEC CO.. LTD.; Manuftr: CYN; Part_Type: *LF_Resistor; RD_CMPLS_LVL: EP(V1); TOLERANCE: 1%; WATTAGE: 1/16W; fp_ECN: 0402 SERIES_LL34.xls
R557 = R: RES CHIP 2.7K 1/16W +-1%(0402); CLASS: DISCRETE; CMPLS_LVL: EP; Data: RHT_LF_RES SERIES-2.pdf; From_pj: S93-MARTIN; Lifecycle: Comp-Approve; MATERIAL: CHIP; Manuf_PN: CR022K70F002S; Manuf_name: RTECH TECHNOLOGY CO..LTD. (Compostar); Manuftr: RHT; Part_Type: *LF_Resistor; TOLERANCE: 1%; WATTAGE: 1/16W; fp_ECN: 0402 SERIES_LL34.xls
R568 = R: RES CHIP 121 1/16W +-1%(0402); CLASS: DISCRETE; CMPLS_LVL: EP; Data: RHT_LF_RES SERIES.pdf; From_pj: S07-CT; Lifecycle: Comp-Approve; MATERIAL: CHIP; Manuf_PN: RR0510S-1210-FN; Manuf_name: CYNTEC CO.. LTD.; Manuftr: CYN; Part_Type: *LF_Resistor; Status: Preferred; TOLERANCE: 1%; WATTAGE: 1/16W; fp_ECN: 0402 SERIES_LL34.xls
R624 = R: RES CHIP 240 1/16W +-5%(0402); CLASS: DISCRETE; CMPLS_LVL: EP; Data: YGO_RC0402 SERIES.pdf; From_pj: TU1B-MARTIN; Lifecycle: Comp-Approve; MATERIAL: CHIP; Manuf_PN: RC0402JR-07240RL; Manuf_name: YAGEO CORPORATION; Manufacturer: CYN; Manuftr: YGO; Part_Type: *LF_Resistor; RD_CMPLS_LVL: EP; TOLERANCE: 5%; WATTAGE: 1/16W; fp_ECN: 0402 SERIES_LL34.xls
R1203 R1204 = R: RES CHIP 1K 1/16W +-1% (0402); CLASS: DISCRETE; CMPLS_LVL: EP; Data: WTC_LF_WR SERIES.pdf; Lifecycle: Comp-Approve; MATERIAL: CHIP; Manuf_PN: RR0510S-102-FN; Manuf_name: CYNTEC CO.. LTD.; Manuftr: CYN; Not_insert: NI; Part_Type: *LF_Resistor; Status: Preferred; TOLERANCE: 1%; WATTAGE: 1/16W; fp_ECN: 0402 SERIES_LL34.xls
U11 = SCHOTTKY_DUAL_12A_3C: DIODE SMD BAT54CW(30V,0.2A,SOT323); CLASS: IC; CMPLS_LVL: EP(V1); Data: PJT_BAT54CW-SERIES.pdf; From_pj: TU1H-JAMIE; MATERIAL: IC; Manuf_name: PAN JIT INTERNATIONAL INC.; Manuftr: PJT; Part_Type: *LF_Semiconductor; RD_CMPLS_LVL: EP(V1)
C129 = CAP_NP: CAP CHIP 0.1U 16V(10%.X7R.0402); CLASS: DISCRETE; CMPLS_LVL: EP(V1); Data: MUR_LF_CAP SERIES_1.pdf; From_pj: S5A-TRAVIS; Lifecycle: Comp-Approve; MATERIAL: X7R; Manuf_PN: WBM155R71C104K; Manuf_name: MURATA ERIE N.A. INC TAIWAN BRANCH Okayama Murata Mfg.Co..Ltd. Wakura Murata Mfg; Manuftr: MUR; Part_Type: *LF_C0402; RD_CMPLS_LVL: EP(V1); TOLERANCE: 10%; VOLTAGE: 16V; fp_ECN: 0402 SERIES_LL34.xls
C255 C300 C461 C480 C481 = CAP_NP: CAP CHIP 0.1U 10V(+-10%.X7R.0402); CLASS: DISCRETE; CMPLS_LVL: EP; Data: RHT_LF_CAP SERIES-1.pdf; From_pj: S82-ICE; Lifecycle: Comp-Approve; MATERIAL: X7R; Manuf_PN: GRM155R71A104K; Manuf_name: "MURATA ERIE N.A. INC TAIWAN BRANCH Okayama Murata Mfg.Co..Ltd.Wakura Murata Mfg; Manuftr: MUR; Part_Type: *LF_C0402; Standard: ##; Status: Preferred; TOLERANCE: 10%; VOLTAGE: 10V; fp_ECN: 0402 SERIES_LL34.xls
R140 R148 R155 R528 = R: RES CHIP 51 1/16W +-5%(0402); CLASS: DISCRETE; CMPLS_LVL: EP; Data: TAI_LF_RM SERIES.pdf; Lifecycle: Comp-Approve; MATERIAL: CHIP; Manuf_PN: RR0510S-510-JN; Manuf_name: CYNTEC CO.. LTD.; Manuftr: CYN; Not_insert: NI; Part_Type: *LF_Resistor; Status: Preferred; TOLERANCE: 5%; WATTAGE: 1/16W; fp_ECN: 0402 SERIES_LL34.xls
R299 R301 R302 R401 R402 R677 R767 R777 = R: RES CHIP 51 1/16W +-5%(0402); CLASS: DISCRETE; CMPLS_LVL: EP; Data: TAI_LF_RM SERIES.pdf; Lifecycle: Comp-Approve; MATERIAL: CHIP; Manuf_PN: RR0510S-510-JN; Manuf_name: CYNTEC CO.. LTD.; Manuftr: CYN; Part_Type: *LF_Resistor; Status: Preferred; TOLERANCE: 5%; WATTAGE: 1/16W; fp_ECN: 0402 SERIES_LL34.xls
R340 = R: RES CHIP 953 1/16W +-1% (0402); CLASS: DISCRETE; CMPLS_LVL: EP(V1); Data: RR0510S.pdf; From_pj: F01-DANNY; Lifecycle: Comp-Approve; MATERIAL: CHIP; Manuf_PN: RR0510S-9530-FN; Manuf_name: CYNTEC CO.. LTD.; Manuftr: CYN; Part_Type: *LF_Resistor; RD_CMPLS_LVL: EP; TOLERANCE: 1%; WATTAGE: 1/16W; fp_ECN: 0402 SERIES_LL34.xls
R369 = R: RES CHIP 51(1/20W,+-1%,0201); CLASS: DISCRETE; CMPLS_LVL: EP(V1); Data: YGO_RC0201FR-0751RL.pdf; From_pj: F07-HENRY; Lifecycle: Comp-Approve; MATERIAL: CHIP; Manuf_PN: RC0201FR-0751RL; Manuf_name: YAGEO CORPORATION; Manuftr: YGO; Part_Type: *LF_Resistor; RD_CMPLS_LVL: EP(V1); TOLERANCE: 1%; WATTAGE: 1/20W
R769 = R: RES CHIP 150 1/16W +-1%(0402); CLASS: DISCRETE; CMPLS_LVL: EP; Data: WTC_LF_WR SERIES.pdf; From_pj: S07-CT; Lifecycle: Comp-Approve; MATERIAL: CHIP; Manuf_PN: RR0510S-151-FN; Manuf_name: CYNTEC CO.. LTD.; Manuftr: CYN; Part_Type: *LF_Resistor; Status: Preferred; TOLERANCE: 1%; WATTAGE: 1/16W; fp_ECN: 0402 SERIES_LL34.xls
J41 = SCONN260_ADDR0106P003A: CONN SMD HS DDR4 260P 2R FR(P0.5,H9.2); CLASS: IO; Data: LTS_ADDR0111-P007A.pdf; From_pj: T6A-TONY; Lifecycle: Comp-Release Qty; MATERIAL: IO; Manuf_PN: ADDR0111-P007A; Manuf_name: LOTES(CHIA TSE TERMINAL INDUSTRYLOTES SUZHOU CO.,; Manuftr: LTS; Part_Type: *LF_Connector; RD_CMPLS_LVL: EP(V1)
C21 = CAP_NP: CAP CHIP 0.01U 50V(+-10%,X7R,0402); CLASS: DISCRETE; CMPLS_LVL: EP(V1); Data: MUR_MLCC_20110826.pdf; From_pj: T2B-CHEESE; Lifecycle: Comp-Approve; MATERIAL: X7R; Manuf_PN: WBM155R71H103K; Manuf_name: MURATA ERIE N.A. INC TAIWAN BRANCH Okayama Murata Mfg.Co.,Ltd.; Manufacturer: MUR; Manuftr: MUR; Part_Type: *LF_C0402; RD_CMPLS_LVL: EP(V1); ROOM: VR_P1V05_PCH; TOLERANCE: 10%; Top_bot: TOP; VOLTAGE: 50V; fp_ECN: 0402 SERIES_LL34.xls
R15 = R: RES CHIP 2.0 1/16W +1%(0402); CLASS: DISCRETE; CMPLS_LVL: EP(V1); Data: WTC_resistors_20080905.pdf; From_pj: S2B-YU-LIN; Lifecycle: Comp-Approve; MATERIAL: CHIP; Manuf_PN: WR04W2R00FTL; Manuf_name: WALSIN TECHNOLOGY CORPORATION; Manuftr: WTC; Part_Type: *LF_Resistor; RD_CMPLS_LVL: EP(V1); TOLERANCE: 1%; WATTAGE: 1/16W; fp_ECN: 0402 SERIES_LL34.xls
U92 = EPM570M100C5N: PROG IC (100P) EPM240M100C5N (MBGA); CLASS: IC; Data: ATA_EPM570M100C5N.pdf; From_pj: S2B-HANK; Lifecycle: Comp-Approve; MATERIAL: IC; Manuf_name: ALTERA; Manuftr: ATA; Part_Type: *LF_Chipset; RD_CMPLS_LVL: EU(V1); Standard: Non-Preferred; fp_ECN: BGA100XD_SMDC9_SM9.msg
JP4 = SCONN8_5013310807: CONN SMD HRADER 8P 1R MR(P1.25,H3.4); CLASS: IO; CMPLS_LVL: EP(V1); Data: ACS_50271-0080N-V05.pdf; From_pj: F0B-TONY; Lifecycle: P/N Release; MATERIAL: IO; Manuf_PN: 50271-0080N-V05; Manuf_name: ACES ELECTRONIC CO., LTD.; Manuftr: ACS; Part_Type: *LF_Connector; RD_CMPLS_LVL: EP(V1)
R52 R733 = R: RES CHIP 22.1 1/16W +-1%(0402) L-F; CLASS: DISCRETE; CMPLS_LVL: EP; Data: WTC_LF_WR SERIES-4.pdf; From_pj: YK1-KEVIN; MATERIAL: CHIP; Manuf_PN: WR04X22R1FTL; Manuf_name: WALSIN TECHNOLOGY CORPORATION; Manuftr: WTC; Part_Type: *LF_Resistor; TOLERANCE: 1%; WATTAGE: 1/16W; fp_ECN: 0402 SERIES_LL34.xls
R1124 = R: RESISTOR CHIP 0 1/16W +-5%(0402); CLASS: DISCRETE; CMPLS_LVL: EP; Data: WTC_LF_WR SERIES.pdf; Lifecycle: Comp-Approve; MATERIAL: CHIP; Manuf_PN: RR0510X-000-XN; Manuf_name: CYNTEC CO.. LTD.; Manuftr: CYN; Part_Type: *LF_Resistor; Status: Preferred; TOLERANCE: 5%; WATTAGE: 1/16W; fp_ECN: 0402 SERIES_LL34.xls
R1128 = R: RES CHIP 2.21K 1/16W +-1% (0402); CLASS: DISCRETE; CMPLS_LVL: EP; Data: WTC_LF_WR SERIES-4.pdf; From_pj: TU1-SUNGHSIN; Lifecycle: Comp-Approve; MATERIAL: CHIP; Manuf_PN: WR04X2211FTL; Manuf_name: WALSIN TECHNOLOGY CORPORATION; Manuftr: WTC; Part_Type: *LF_Resistor; TOLERANCE: 1%; WATTAGE: 1/16W; fp_ECN: 0402 SERIES_LL34.xls
R1130 R1172 R1173 = R: RES CHIP 49.9 1/16W +-1% (0402); CLASS: DISCRETE; CMPLS_LVL: EP; Data: WTC_LF_WR SERIES.pdf; Lifecycle: Comp-Approve; MATERIAL: CHIP; Manuf_PN: RR0510S-49R9-FN; Manuf_name: CYNTEC CO.. LTD.; Manuftr: CYN; Part_Type: *LF_Resistor; Status: Preferred; TOLERANCE: 1%; WATTAGE: 1/16W; fp_ECN: 0402 SERIES_LL34.xls
R1177-R1184 R1186 = R: RES CHIP 100K 1/16W +-1% (0402); CLASS: DISCRETE; CMPLS_LVL: EP; Data: WTC_LF_WA06X SERIES.pdf; From_pj: S30-SP; Lifecycle: Comp-Approve; MATERIAL: CHIP; Manuf_PN: RR0510S-104-FN; Manuf_name: CYNTEC CO.. LTD.; Manuftr: CYN; Part_Type: *LF_Resistor; Status: Preferred; TOLERANCE: 1%; WATTAGE: 1/16W; fp_ECN: 0402 SERIES_LL34.xls
R1185 = R: RES CHIP 100K 1/16W +-1% (0402); CLASS: DISCRETE; CMPLS_LVL: EP; Data: WTC_LF_WA06X SERIES.pdf; From_pj: S30-SP; Lifecycle: Comp-Approve; MATERIAL: CHIP; Manuf_PN: RR0510S-104-FN; Manuf_name: CYNTEC CO.. LTD.; Manuftr: CYN; Not_insert: NI; Part_Type: *LF_Resistor; Status: Preferred; TOLERANCE: 1%; WATTAGE: 1/16W; fp_ECN: 0402 SERIES_LL34.xls
U90 = SN74LVC1G07: IC OTHER(5P)SN74LVC1G07DCKR(SOT); CLASS: IC; CMPLS_LVL: EP(V1); Data: TIC_SN74LVC1G07DCKR.pdf; From_pj: S50-STEVE; Lifecycle: Comp-Approve; MATERIAL: IC; Manuf_name: TEXAS INSTRUMENTS SUPPLY CO..; Manuftr: TIC; Part_Type: *LF_Chipset; RD_CMPLS_LVL: EP(V1); Standard: Potential
C118 = CAP_NP: CAP CHIP 1UF 25V(+-10%,X6S,0402); CLASS: DISCRETE; CMPLS_LVL: EP(V1); Data: MUR_GRM155R72A221KA01-01.pdf; From_pj: F06-RAYMOND; Lifecycle: Comp-Approve; MATERIAL: X6S; Manuf_PN: GRM155C81E105K; Manuf_name: MURATA ERIE N.A. INC TAIWAN BRANCH Okayama Murata Mfg.Co..Ltd.Wakura Murata Mfg.; Manuftr: MUR; Part_Type: *LF_C0402; RD_CMPLS_LVL: EP(V1); TOLERANCE: 10%; VOLTAGE: 25V; fp_ECN: 0402 SERIES_LL34.xls
C663 C664 C667 = CAP_NP: CAP CHIP 10U 25V(+-10%,X7R,1206)MUR; CLASS: DISCRETE; CMPLS_LVL: EP(V1); Data: GRM31CR71E106K.pdf; From_pj: T2H-CF; Lifecycle: Comp-Release Qty; MATERIAL: X7R; Manuf_PN: GRM31CR71E106K; Manuf_name: MURATA ERIE N.A. INC TAIWAN BRANCH Okayama Murata Mfg.Co.,Ltd.Wakura Murata Mfg.; Manufacturer: MAT; Manuftr: MUR; Part_Type: *LF_C1206; RD_CMPLS_LVL: EP(V1); REUSE_ANNOTATE: TRUE; TOLERANCE: 10%; VOLTAGE: 25V
C665 C666 C668 = CAP_NP: CAP CHIP 0.1U 25V(+-10%,X7R,0402); CLASS: DISCRETE; Data: YGO_CA-CC-SC SERIES.pdf; From_pj: F03-KC; Lifecycle: Comp-Approve; MATERIAL: X7R; Manuf_PN: CC0402KRX7R8BB104; Manuf_name: YAGEO CORPORATION; Manufacturer: MAT; Manuftr: YGO; Part_Type: *LF_C0402; RD_CMPLS_LVL: EP(V1); REUSE_ANNOTATE: TRUE; SIDE: TOP; Standard: End of Design; TOLERANCE: 10%; Top_Bot: TOP; VOLTAGE: 25V; fp_ECN: 0402 SERIES_LL34.xls
R352 = R: RES CHIP 22.1K 1/16W +-1%(0402); CLASS: DISCRETE; CMPLS_LVL: EP; Data: CYN-RR0510(0402) SERIES.pdf; From_pj: TU1-SUNGHSIN; Lifecycle: Comp-Approve; MATERIAL: CHIP; Manuf_PN: RR0510S-2212-FN; Manuf_name: CYNTEC CO.. LTD.; Manuftr: CYN; Part_Type: *LF_Resistor; Standard: ##; TOLERANCE: 1%; WATTAGE: 1/16W; fp_ECN: 0402 SERIES_LL34.xls
R1025 = R: RESISTOR CHIP 0 1/10W+-5%(0603); CLASS: DISCRETE; CMPLS_LVL: EP; Data: WTC_LF_WR SERIES.pdf; Lifecycle: Comp-Approve; MATERIAL: CHIP; Manuf_PN: CRCW06030000Z0EA; Manuf_name: DALE ELECTRONICS.INC.; Manuftr: DAL; Part_Type: *LF_Resistor; Standard: ##; Status: Normal; TOLERANCE: 5%; WATTAGE: 1/10W
R1312 = R: RES CHIP 47K 1/16W +-5% (0402); CLASS: DISCRETE; CMPLS_LVL: EP; Data: WTC_LF_WR SERIES-4.pdf; From_pj: S93-MARTIN; Lifecycle: Comp-Approve; MATERIAL: CHIP; Manuf_PN: WR04X473 JTL; Manuf_name: WALSIN TECHNOLOGY CORPORATION; Manuftr: WTC; Not_insert: NI; Part_Type: *LF_Resistor; TOLERANCE: 5%; WATTAGE: 1/16W; fp_ECN: 0402 SERIES_LL34.xls
R1364 = R: RESISTOR CHIP 0 1/16W +-5%(0402); BOM: TI; CLASS: DISCRETE; CMPLS_LVL: EP; Data: WTC_LF_WR SERIES.pdf; Lifecycle: Comp-Approve; MATERIAL: CHIP; Manuf_PN: RR0510X-000-XN; Manuf_name: CYNTEC CO.. LTD.; Manufacturer: CYN; Manuftr: CYN; Part_Type: *LF_Resistor; Status: Preferred; TOLERANCE: 5%; WATTAGE: 1/16W; fp_ECN: 0402 SERIES_LL34.xls; top_bot: TOP
R1409 R1410 = R: RESISTOR CHIP 0 1/16W +-5%(0402); CLASS: DISCRETE; CMPLS_LVL: EP; Data: WTC_LF_WR SERIES.pdf; Lifecycle: Comp-Approve; MATERIAL: CHIP; Manuf_PN: RR0510X-000-XN; Manuf_name: CYNTEC CO.. LTD.; Manuftr: CYN; Not_insert: NI; Part_Type: *LF_Resistor; Status: Preferred; TOLERANCE: 5%; WATTAGE: 1/16W; fp_ECN: 0402 SERIES_LL34.xls
J43 = SCONN440_QT01220610413H: CONN SMD HOUSING 440P 4R FS(P0.5,H3.25); CLASS: IO; Data: FOX_QT012206-1041-3H.pdf; From_pj: F0B-WILLIAM; Lifecycle: Comp-Release Qty; MATERIAL: IO; Manuf_PN: QT012206-1041-3H; Manuf_name: (FOXCONN) HON HAI PRECISION INDUSTRY KANG ZHUN PRESION TOOLING(KUN SHAN)CO..LTD; Manuftr: FOX; Part_Type: *LF_Connector; RD_CMPLS_LVL: EP(V1); Standard: Non-Preferred

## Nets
GND: C21.2 C63.2 C71.1 C75.1 C77.1 C78.1 C118.2 C129.2 C255.2 C274.1 C277.1 C300.2 C461.2 C480.2 C481.2 C606.1 C663.2 C664.2 C665.2 C666.2 C667.2 C668.2 J41.1(VSS_0) J41.2(VSS_21) J41.5(VSS_1) J41.6(VSS_22) J41.9(VSS_2) J41.10(VSS_23) J41.14(VSS_24) J41.15(VSS_3) J41.18(VSS_25) J41.19(VSS_4) J41.22(VSS_26) J41.23(VSS_5) J41.26(VSS_27) J41.27(VSS_6) J41.30(VSS_28) J41.31(VSS_7) J41.35(VSS_8) J41.36(VSS_29) J41.39(VSS_9) J41.40(VSS_30) J41.43(VSS_10) J41.44(VSS_31) J41.47(VSS_11) J41.48(VSS_32) J41.51(VSS_12) J41.52(VSS_33) J41.56(VSS_34) J41.57(VSS_13) J41.60(VSS_35) J41.61(VSS_14) J41.64(VSS_36) J41.65(VSS_15) J41.68(VSS_37) J41.69(VSS_16) J41.72(VSS_38) J41.73(VSS_17) J41.77(VSS_18) J41.78(VSS_39) J41.81(VSS_19) J41.82(VSS_40) J41.85(VSS_20) J41.86(VSS_41) J41.89(VSS_42) J41.90(VSS_49) J41.93(VSS_43) J41.94(VSS_50) J41.98(VSS_51) J41.99(VSS_44) J41.102(VSS_52) J41.103(VSS_45) J41.106(VSS_53) J41.107(VSS_46) J41.167(VSS_47) J41.168(VSS_54) J41.171(VSS_48) J41.172(VSS_55) J41.175(VSS_56) J41.176(VSS_75) J41.180(VSS_76) J41.181(VSS_57) J41.184(VSS_77) J41.185(VSS_58) J41.188(VSS_78) J41.189(VSS_59) J41.192(VSS_79) J41.193(VSS_60) J41.196(VSS_80) J41.197(VSS_61) J41.201(VSS_62) J41.202(VSS_81) J41.205(VSS_63) J41.206(VSS_82) J41.209(VSS_64) J41.210(VSS_83) J41.213(VSS_65) J41.214(VSS_84) J41.217(VSS_66) J41.218(VSS_85) J41.222(VSS_86) J41.223(VSS_67) J41.226(VSS_87) J41.227(VSS_68) J41.230(VSS_88) J41.231(VSS_69) J41.234(VSS_89) J41.235(VSS_70) J41.238(VSS_90) J41.239(VSS_71) J41.243(VSS_72) J41.244(VSS_91) J41.247(VSS_73) J41.248(VSS_92) J41.251(VSS_74) J41.252(VSS_93) J41.G1 J41.G2 J43.A41(GND) J43.A51(GND) J43.A57 J43.A60(GND) J43.A66 J43.A67 J43.A70(GND) J43.A73 J43.A76 J43.A79 J43.A80(GND) J43.A83 J43.A87 J43.A90(GND) J43.A100(GND) J43.A110(GND) J43.B41(GND) J43.B51(GND) J43.B57 J43.B60(GND) J43.B63 J43.B70(GND) J43.B73 J43.B76 J43.B79 J43.B80(GND) J43.B83 J43.B90(GND) J43.B100(GND) J43.B110(GND) JP4.3 JP4.8 JP4.G1 JP4.G2 R11.2 R148.1 R225.2 R236.2 R301.1 R550.1 R556.1 R568.1 R1126.2 R1129.2 R1131.1 R1133.2 R1134.2 R1177.1 R1178.1 R1179.1 R1180.1 R1181.1 R1182.1 R1183.1 R1184.1 R1185.1 R1186.1 R1312.1 R1409.2 R1410.2 U15.2(GND) U16.2(GND) U30.AA14(VSS533) U30.AA16(VSS534) U30.AA19(VSS530) U30.AG21(VSS542) U30.AK12(VSS543) U30.B3(VSS531) U30.B61(VSS416) U30.B76(VSS436) U30.BM58(VSS432) U30.BN56(VSS435) U30.BT58(VSS479) U30.BV56(VSS520) U30.CB35(VSS280) U30.CB47(VSS281) U30.CB51(VSS282) U30.CB54(VSS283) U30.CB58(VSS284) U30.CB62(VSS285) U30.CC5(VSS292) U30.CC11(VSS286) U30.CC30(VSS287) U30.CC33(VSS288) U30.CC37(VSS289) U30.CC41(VSS290) U30.CC45(VSS291) U30.CC74(VSS293) U30.CD16(VSS294) U30.CD43(VSS295) U30.CD47(VSS296) U30.CD62(VSS297) U30.CE1(VSS298) U30.CE3(VSS299) U30.CE5(VSS300) U30.CE74(VSS301) U30.CF11(VSS302) U30.CF30(VSS303) U30.CG5(VSS308) U30.CG16(VSS304) U30.CG20(VSS305) U30.CG24(VSS306) U30.CG28(VSS307) U30.CG62(VSS309) U30.CG66(VSS310) U30.CG69(VSS311) U30.CG72(VSS312) U30.CG74(VSS313) U30.CH11(VSS314) U30.CH18(VSS315) U30.CH22(VSS316) U30.CH26(VSS317) U30.CH30(VSS318) U30.CH64(VSS319) U30.CH67(VSS320) U30.CH71(VSS321) U30.CH75(VSS322) U30.CH77(VSS323) U30.CJ5(VSS325) U30.CJ16(VSS324) U30.CJ62(VSS326) U30.CJ74(VSS327) U30.CK11(VSS328) U30.CK30(VSS329) U30.CL5(VSS331) U30.CL16(VSS330) U30.CL62(VSS332) U30.CL74(VSS333) U30.CM1(VSS334) U30.CM11(VSS335) U30.CM30(VSS336) U30.CN5(VSS337) U30.CN74(VSS338) U30.CP1(VSS339) U30.CP2(VSS344) U30.CP7(VSS357) U30.CP9(VSS362) U30.CP12(VSS340) U30.CP14(VSS341) U30.CP16(VSS342) U30.CP18(VSS343) U30.CP20(VSS345) U30.CP23(VSS346) U30.CP25(VSS347) U30.CP27(VSS348) U30.CP29(VSS349) U30.CP31(VSS350) U30.CP34(VSS351) U30.CP36(VSS352) U30.CP64(VSS354) U30.CP66(VSS355) U30.CP70(VSS358) U30.CP72(VSS359) U30.CP77(VSS360) U30.CP78(VSS361) U30.CR1(VSS363) U30.CR2(VSS364) U30.CR3(VSS366) U30.CR5(VSS368) U30.CR21(VSS365) U30.CR37(VSS367) U30.CR77(VSS369) U30.CR78(VSS370) U30.CT14(VSS371) U30.CT29(VSS372) U30.CT70(VSS373) U30.CU1(VSS374) U30.CU2(VSS375) U30.CU3(VSS377) U30.CU21(VSS376) U30.CU37(VSS378) U30.CU77(VSS379) U30.CU78(VSS380) U30.CV2(VSS382) U30.CV3(VSS384) U30.CV5(VSS385) U30.CV6(VSS386) U30.CV14(VSS381) U30.CV29(VSS383) U30.CV70(VSS387) U30.CV73(VSS388) U30.CV74(VSS389) U30.CV76(VSS390) U30.CV77(VSS391) U30.D5(VSS532) U30.D48(VSS521) U30.D61(VSS392) U30.E1(VSS393) U30.E2(VSS398) U30.E5(VSS413) U30.E7(VSS423) U30.E9(VSS429) U30.E12(VSS394) U30.E14(VSS395) U30.E16(VSS396) U30.E18(VSS397) U30.E20(VSS399) U30.E23(VSS400) U30.E25(VSS401) U30.E27(VSS402) U30.E29(VSS403) U30.E31(VSS404) U30.E34(VSS405) U30.E36(VSS406) U30.E38(VSS407) U30.E40(VSS408) U30.E42(VSS409) U30.E44(VSS410) U30.E47(VSS411) U30.E49(VSS412) U30.E51(VSS414) U30.E53(VSS415) U30.E58(VSS417) U30.E60(VSS418) U30.E62(VSS419) U30.E64(VSS420) U30.E66(VSS421) U30.E68(VSS422) U30.E70(VSS424) U30.E74(VSS426) U30.E77(VSS427) U30.E78(VSS428) U30.F1(VSS430) U30.H56(VSS425) U30.H60(VSS433) U30.H67(VSS434) U30.J3(VSS529) U30.J72(VSS437) U30.J74(VSS438) U30.K4(VSS535) U30.K56(VSS431) U30.K60(VSS439) U30.K67(VSS440) U30.L1(VSS536) U30.L5(VSS451) U30.L9(VSS457) U30.L13(VSS441) U30.L16(VSS442) U30.L20(VSS443) U30.L24(VSS444) U30.L28(VSS445) U30.L32(VSS446) U30.L35(VSS447) U30.L39(VSS448) U30.L43(VSS449) U30.L47(VSS450) U30.L51(VSS452) U30.L58(VSS453) U30.L62(VSS454) U30.L66(VSS455) U30.L74(VSS456) U30.M7(VSS473) U30.M11(VSS458) U30.M14(VSS459) U30.M18(VSS460) U30.M22(VSS461) U30.M26(VSS462) U30.M30(VSS463) U30.M33(VSS464) U30.M37(VSS465) U30.M41(VSS466) U30.M45(VSS467) U30.M49(VSS468) U30.M52(VSS469) U30.M56(VSS470) U30.M60(VSS471) U30.M64(VSS472) U30.M71(VSS474) U30.N5(VSS475) U30.N66(VSS476) U30.N74(VSS477) U30.N76(VSS478) U30.P52(VSS480) U30.P60(VSS481) U30.R35(VSS482) U30.R37(VSS483) U30.R40(VSS484) U30.R42(VSS485) U30.R54(VSS486) U30.R66(VSS487) U30.R69(VSS488) U30.T5(VSS492) U30.T11(VSS489) U30.T33(VSS490) U30.T39(VSS491) U30.T60(VSS493) U30.T74(VSS494) U30.U9(VSS502) U30.U13(VSS495) U30.U16(VSS496) U30.U20(VSS497) U30.U24(VSS498) U30.U28(VSS499) U30.U32(VSS500) U30.U66(VSS501) U30.V1(VSS537) U30.V3(VSS538) U30.V5(VSS512) U30.V7(VSS517) U30.V14(VSS503) U30.V18(VSS504) U30.V22(VSS505) U30.V26(VSS506) U30.V30(VSS507) U30.V35(VSS508) U30.V42(VSS509) U30.V44(VSS510) U30.V46(VSS511) U30.V55(VSS513) U30.V60(VSS514) U30.V62(VSS515) U30.V64(VSS516) U30.V71(VSS518) U30.W13(VSS539) U30.W16(VSS540) U30.W24(VSS541) U30.Y5(VSS525) U30.Y39(VSS522) U30.Y40(VSS523) U30.Y42(VSS524) U30.Y55(VSS526) U30.Y74(VSS527) U30.Y76(VSS528) U63.1(1OE_N) U63.4(1DIR) U63.10(GND_1) U63.11(GND_2) U63.16(2OE_N) U90.3(GND) U92.C5(GNDINT_3) U92.D5(GNDIO_1) U92.D7(GNDIO_2) U92.E4(GNDIO_3) U92.E8(GNDINT_1) U92.G4(GNDINT_2) U92.G8(GNDIO_4) U92.H5(GNDIO_5) U92.H7(GNDIO_6) U92.J5(GNDINT_4) ; also on sheet 1 2 3 4 11 12 20 22 23 24 25 26 27 28 31 32 41 42 45 46 47 48 49 50 51 52 53 54 55 56 57 58 59 60 61 62 63 64 65 66 67 68 69 70 71 72 73 74 75 77 79 81 82 83 84 86 87 88 92
P0V6_DDR4_VREF_CA_CHAB: R11.1 R14.2 R15.2 ; also on sheet 60 61
P1V05_COMBINED: C78.2 C129.1 C277.2 R140.1 R155.1 R211.2 R238.1 R253.1 R299.1 R302.1 R340.1 R369.1 R388.1 R398.1 R401.1 R402.1 R403.1 R525.2 R528.1 R557.1 R624.1 R645.1 R677.1 R767.1 R769.2 R777.1 U16.1(VCC_A) U63.2(VCC_B) ; also on sheet 1 3 4 41 42 45 47 48 50 51 52 54 55 56 63 71 74 75 79 84 92 94
P2V5_VPP: C75.2 J41.257(VPP_1) J41.259(VPP_0) R81.1 U15.1(VCC_A) U15.5(DIR) ; also on sheet 11 25 60 61 75
P3V3: C71.2 U16.6(VCC_B) ; also on sheet 4 20 32 41 42 46 47 49 50 52 55 56 63 67 74 77 81
P3V3_STBY: C77.2 C274.2 C606.2 J43.A91 JP4.1 R121.1 R143.1 R186.2 R214.1 R478.2 R545.1 R567.1 R571.1 R574.1 R576.1 R580.1 R588.1 R686.2 R772.2 R1123.2 R1132.2 R1203.1 R1204.1 R1358.1 R1359.1 R1360.1 R1399.1 U11.2(A) U15.6(VCC_B) U63.3(VCC_A) U63.5(2DIR) U90.5(VCC) U92.C4(VCCIO2_1) U92.C7(VCCINT_3) U92.C8(VCCIO2_2) U92.E3(VCCIO1_1) U92.E9(VCCINT_1) U92.G3(VCCINT_2) U92.G9(VCCIO2_3) U92.J4(VCCIO1_2) U92.J7(VCCINT_4) U92.J8(VCCIO1_3) ; also on sheet 3 4 20 22 24 25 26 27 28 31 32 41 52 55 56 57 58 59 62 63 64 65 67 68 69 70 71 72 73 74 75 77 79 81 82 84 86 87 88 92
P3V_BAT: C63.1 R228.2 R352.1 U11.3(C) ; also on sheet 41 52 63 72
P3V_BAT_R: R46.2 U11.1(B) ; also on sheet 74
P5V_STBY: C667.1 C668.1 J43.B84 J43.B85 J43.B86 J43.B87 ; also on sheet 1 2 23 26 31 70 74 84
P12V_STBY_CONN: C663.1 C664.1 C665.1 C666.1 J43.A104 J43.A105 J43.A106 J43.A107 J43.A108 J43.A109 J43.B104 J43.B105 J43.B106 J43.B107 J43.B108 J43.B109 ; also on sheet 12 86
VBAT: R46.1 R1025.1
VBAT_RR: J43.A47 R1025.2
CLK_100M_PE_A_DN: J43.A89 ; also on sheet 49
CLK_100M_PE_A_DP: J43.A88 ; also on sheet 49
CLK_CPLD_SUSCLK: U92.G11(GCLK_3) ; also on sheet 41 47
COM_MB_RX_R: J43.A99 R1253.2
COME_GPI0: J43.A54 ; also on sheet 20
DDR3_4_STRAP: R624.2 U30.AK69(DDR3_4_STRAP)
DRAM_PWROK: R557.2 U30.CV55(DRAM_PWR_OK) ; also on sheet 47
FM_BDXDE_SLP3_CPU_N: R1128.2 R1129.1 ; also on sheet 47
FM_BDXDE_SLP3_N: R1128.1 ; also on sheet 20 63 64 71
FM_CPLD_CPU_DIMM_EVENT_CO_N: R843.2 ; also on sheet 64 72
FM_CPLD_CPU_DIMM_EVENT_CO_R_N: R843.1 U15.4(B)
FM_CPLD_FAST_PROCHOT_N_R: R1124.1 ; also on sheet 64
FM_CPLD_P0V6_VTT_DIMM_EN: R1170.2 R1184.2 ; also on sheet 22
FM_CPLD_P0V6_VTT_DIMM_EN_R: R1170.1 ; also on sheet 64
FM_CPLD_P1V2_VDDQ_EN: R1160.2 R1183.2 ; also on sheet 24
FM_CPLD_P1V2_VDDQ_EN_R: R1160.1 ; also on sheet 64
FM_CPLD_P1V05_COMBINED_EN: R1153.2 R1182.2 ; also on sheet 3
FM_CPLD_P1V05_COMBINED_EN_R: R1153.1 ; also on sheet 64
FM_CPLD_P1V5_PCH_EN: R1164.2 R1180.2 ; also on sheet 31
FM_CPLD_P1V05_PCH_EN: R1162.2 R1186.2 ; also on sheet 84
FM_CPLD_P1V5_PCH_EN_R: R1164.1 ; also on sheet 64
FM_CPLD_P1V05_PCH_EN_R: R1162.1 ; also on sheet 64
FM_CPLD_P2V5_VPP_EN: R1166.2 R1178.2 ; also on sheet 25
FM_CPLD_P2V5_VPP_EN_R: R1166.1 ; also on sheet 64
FM_CPLD_P3V3_EN_N: R1168.2 R1185.2 ; also on sheet 32
FM_CPLD_P3V3_EN_N_R: R1168.1 ; also on sheet 64
FM_CPLD_PVCCIN_EN: R1173.1 R1181.2 ; also on sheet 3
FM_CPLD_PVCCIN_EN_R: R1173.2 ; also on sheet 64
FM_CPLD_PVCCKRHV_EN: R1149.2 R1179.2 ; also on sheet 26
FM_CPLD_PVCCKRHV_EN_R: R1149.1 ; also on sheet 64
FM_CPLD_PVCCSCFUSESUS_EN: R1146.2 R1177.2 ; also on sheet 27
FM_CPLD_PVCCSCFUSESUS_EN_R: R1146.1 ; also on sheet 64
FM_FAST_PROCHOT_N: R1124.2 ; also on sheet 55 71
FM_LVC3_RISER1_ID4_N_PU: R545.2 ; also on sheet 46
FM_USB_OC_0_N: R576.2 ; also on sheet 46 65
FM_USB_OC_1_N: R574.2 ; also on sheet 46 65
FM_USB_OC_2_N: R571.2 ; also on sheet 46
FM_USB_OC_3_N: R567.2 ; also on sheet 46
FM_USB_OC_4_N: R1359.2 ; also on sheet 46
FM_USB_OC_5_N: R1360.2 ; also on sheet 46
FM_USB_OC_6_N: R1358.2 ; also on sheet 46
H_MEM_EVENT_CO_N: R844.1 ; also on sheet 60 61
H_MEM_EVENT_CO_R_N: R81.2 R844.2 U15.3(A)
INTRUDER_N: R228.1 U30.AK2(INTRUDER_N)
IRQ_ILB_SEIRQ_BDE: R68.2 ; also on sheet 47 63
IRQ_ILB_SEIRQ_BDE_R: R68.1 R1244.1 R1420.1 U16.4(B)
IRQ_ILB_SEIRQ_BMC: R1420.2 ; also on sheet 72
IRQ_ILB_SEIRQ_COME: J43.A50 R1244.2
JTAG_CPLD_TCK: JP4.2 R52.1 ; also on sheet 71
JTAG_CPLD_TCK_R: R52.2 R1131.2 U92.K1(TCK)
JTAG_CPLD_TDI: JP4.7 R1123.1 U92.J2(TDI) ; also on sheet 71
JTAG_CPLD_TDO: JP4.4 U92.K2(TDO) ; also on sheet 71
JTAG_CPLD_TMS: JP4.5 R733.1 ; also on sheet 71
JTAG_CPLD_TMS_R: R733.2 R1132.1 U92.J1(TMS)
LED_CPLD_D2: U92.F10(GCLK_2) ; also on sheet 77
LED_CPLD_D3: U92.E1(GCLK_1) ; also on sheet 77
LED_CPLD_D4: U92.F2(GCLK_0) ; also on sheet 77
M_AB_RESET_N: U30.CR43(DDR_RESET_N) ; also on sheet 60 61
M_AB_VREF: C21.1 R15.1 U30.CR52(DDR_VREF)
NC_JTAG_CPLDA_7: JP4.6
P2E_G_RX_DN<0>: J43.B72 ; also on sheet 94
P2E_G_RX_DN<1>: J43.B75 ; also on sheet 94
P2E_G_RX_DN<2>: J43.B78 ; also on sheet 94
P2E_G_RX_DN<3>: J43.B82 ; also on sheet 94
P2E_G_RX_DP<0>: J43.B71 ; also on sheet 94
P2E_G_RX_DP<1>: J43.B74 ; also on sheet 94
P2E_G_RX_DP<2>: J43.B77 ; also on sheet 94
P2E_G_RX_DP<3>: J43.B81 ; also on sheet 94
P2E_G_TX_DN<0>: J43.A72 ; also on sheet 94
P2E_G_TX_DN<1>: J43.A75 ; also on sheet 94
P2E_G_TX_DN<2>: J43.A78 ; also on sheet 94
P2E_G_TX_DN<3>: J43.A82 ; also on sheet 94
P2E_G_TX_DP<0>: J43.A71 ; also on sheet 94
P2E_G_TX_DP<1>: J43.A74 ; also on sheet 94
P2E_G_TX_DP<2>: J43.A77 ; also on sheet 94
P2E_G_TX_DP<3>: J43.A81 ; also on sheet 94
P3E_A_RX_DN<0>: J43.B69 ; also on sheet 94
P3E_A_RX_DN<1>: J43.B65 ; also on sheet 94
P3E_A_RX_DN<2>: J43.B62 ; also on sheet 94
P3E_A_RX_DN<3>: J43.B59 ; also on sheet 94
P3E_A_RX_DP<0>: J43.B68 ; also on sheet 94
P3E_A_RX_DP<1>: J43.B64 ; also on sheet 94
P3E_A_RX_DP<2>: J43.B61 ; also on sheet 94
P3E_A_RX_DP<3>: J43.B58 ; also on sheet 94
P3E_A_TX_DN<0>: J43.A69 ; also on sheet 94
P3E_A_TX_DN<1>: J43.A65 ; also on sheet 94
P3E_A_TX_DN<2>: J43.A62 ; also on sheet 94
P3E_A_TX_DN<3>: J43.A59 ; also on sheet 94
P3E_A_TX_DP<0>: J43.A68 ; also on sheet 94
P3E_A_TX_DP<1>: J43.A64 ; also on sheet 94
P3E_A_TX_DP<2>: J43.A61 ; also on sheet 94
P3E_A_TX_DP<3>: J43.A58 ; also on sheet 94
P3E_E_RX_DN<0>: J43.B56 ; also on sheet 94
P3E_E_RX_DN<1>: J43.B53 ; also on sheet 94
P3E_E_RX_DP<0>: J43.B55 ; also on sheet 94
P3E_E_RX_DP<1>: J43.B52 ; also on sheet 94
P3E_E_TX_DN<0>: J43.A56 ; also on sheet 94
P3E_E_TX_DN<1>: J43.A53 ; also on sheet 94
P3E_E_TX_DP<0>: J43.A55 ; also on sheet 94
P3E_E_TX_DP<1>: J43.A52 ; also on sheet 94
PCHHOT_CPU_N: R211.1 U30.BF7(SML1ALERT_N_PCHHOT_N_GPIO74) ; also on sheet 47 56
PD_DDR_RCOMP0: R550.2 U30.CC52(DDR_RCOMP0)
PD_DDR_RCOMP1: R556.2 U30.CD51(DDR_RCOMP1)
PD_DDR_RCOMP2: R568.2 U30.CC49(DDR_RCOMP2)
PU_MBP0_MBPM1_N: R645.2 ; also on sheet 48
PU_SMBALERT_N_GPIO11: R186.1 U30.BH7(SMBALERT_N_GPIO11)
PV_DDR_VTTAB: J41.258(VTT) ; also on sheet 11 22 60 61
PV_VDDRAB: J41.111(VDD_0) J41.112(VDD_9) J41.117(VDD_1) J41.118(VDD_10) J41.123(VDD_2) J41.124(VDD_11) J41.129(VDD_3) J41.130(VDD_12) J41.135(VDD_4) J41.136(VDD_13) J41.141(VDD_5) J41.142(VDD_14) J41.147(VDD_6) J41.148(VDD_15) J41.153(VDD_7) J41.154(VDD_16) J41.159(VDD_8) J41.160(VDD_17) J41.163(VDD_18) R14.1 ; also on sheet 11 22 23 24 51 60 61 74
PWR_BTN_XDP: C255.1 R478.1 ; also on sheet 54 69
PWRGD_APWROK: R1152.2 ; also on sheet 47
PWRGD_APWROK_R: R1152.1 ; also on sheet 64
PWRGD_CPLD_BDXDE_LAN: R1155.2 ; also on sheet 55
PWRGD_CPLD_BDXDE_LAN_R: R1155.1 ; also on sheet 64
PWRGD_CPU: U30.CR39(DDR_PWRGOOD) ; also on sheet 47 54 56 63
PWRGD_PCH_PWROK: J43.B54 R1130.1 R1134.1 ; also on sheet 47 71
PWRGD_PCH_PWROK_R: R1130.2 ; also on sheet 64
RSM_RST_N: R1126.1 R1151.2 ; also on sheet 47 72
RSM_RST_N_R: R1151.1 ; also on sheet 64
RST_BTN_COME_N: J43.B49 ; also on sheet 82
RST_BTN_XDP: C461.1 R686.1 ; also on sheet 54 69
RST_CPLD_CPU_RSMRST_N: R1133.1 U90.2(A) ; also on sheet 64
RST_CPU_RSMRST_N: C300.1 R525.1 ; also on sheet 47
RST_CPU_RSMRST_N_R: U90.4(Y) ; also on sheet 47
RST_PLTRST_COME_N: J43.B50 ; also on sheet 58
RST_RTCRST_N: C118.1 R352.2 R1364.1 ; also on sheet 47
RST_RTCRST_N_R: J43.A63 R1364.2
SERIRQ_DATA: R67.1 ; also on sheet 47
SERIRQ_DATA_R: R67.2 U16.3(A)
SERIRQ_DIR: U16.5(DIR) ; also on sheet 4 47
SMB_BMC_3V3SB_ALRT_N: J43.A93 ; also on sheet 71 73
SMB_DDR01_CLK: U30.CD58(DDR_SCL) ; also on sheet 75
SMB_DDR01_DAT: U30.CC60(DDR_SDA) ; also on sheet 75
SMB_HOST_XDP_CLK: R121.2 U30.BN11(SMBCLK) ; also on sheet 54 62 71 73
SMB_HOST_XDP_DAT: R143.2 U30.BJ13(SMBDATA) ; also on sheet 54 62 71 73
SMB_SML0_3V3SB_ALERT: R214.2 U30.BL7(SML0ALERT_N_GPIO60_MGPIO4)
SMB_SML0_3V3SB_CLK: R1203.2 U30.BR7(SML0DCLK) ; also on sheet 73
SMB_SML0_3V3SB_DAT: R1204.2 U30.BN18(SML0DATA) ; also on sheet 73
SMB_SML1_3V3SB_CLK: R580.2 U30.BG9(SML1CLK_GPIO58_MGPIO11) ; also on sheet 86
SMB_SML1_3V3SB_DAT: R588.2 U30.BB11(SML1DATA_GPIO75_MGPIO12) ; also on sheet 86
SPI_COME_CLK: J43.A94 ; also on sheet 59
SPI_COME_CS0_N: J43.B97 ; also on sheet 59
SPI_COME_MISO: J43.A92 ; also on sheet 59
SPI_COME_MOSI: J43.A95 ; also on sheet 59
TP_BIOS_DIS1_N: J43.B88
TP_M_DDR_VREFDQ0: U30.CV51(DDR_VREFDQ0)
TP_M_DDR_VREFDQ1: U30.CT51(DDR_VREFDQ1)
TP_TYPE10_N: J43.A97 R1312.2
TP_WAKE_0_N: J43.B66 R1409.1
TP_WAKE_1_N: J43.B67 R1410.1
UART1_BDE_R2_TXD: R236.1 R253.2 ; also on sheet 48
UART1_BDE_R_RXD: U63.12(2B2) ; also on sheet 48
UART1_BDE_R_TXD: U63.15(1B1) ; also on sheet 48
UART1_BDE_TXD_R: R1400.2 U63.6(1A1)
UART_BDE_BMC_R_TX: R225.1 R238.2 ; also on sheet 48
UART_BDE_BMC_RX: U63.13(2B1) ; also on sheet 48
UART_BDE_BMC_TX: U63.14(1B2) ; also on sheet 48
UART_BDE_TI_RX: U63.8(2A1) ; also on sheet 70
UART_BDE_TI_TX: R845.1 ; also on sheet 70
UART_BDE_TI_TX_R: R845.2 U63.7(1A2)
UART_COM_MB_RX: R1253.1 R1399.2 U63.9(2A2)
UART_COM_MB_TX: J43.A98 R1400.1
USB2_P0_DN: J43.A45 ; also on sheet 46
USB2_P0_DP: J43.A46 ; also on sheet 46
USB2_P1_DN: J43.B45 ; also on sheet 46
USB2_P1_DP: J43.B46 ; also on sheet 46
USB2_P2_DN: J43.A42 ; also on sheet 46
USB2_P2_DP: J43.A43 ; also on sheet 46
USB2_P3_DN: J43.B42 ; also on sheet 46
USB2_P3_DP: J43.B43 ; also on sheet 46
USB_0_1_OC_N: J43.B44 ; also on sheet 65
USB_2_3_OC_N: J43.A44 ; also on sheet 65
XDP_BDE_PRDY_N: R403.2 ; also on sheet 48 54
XDP_BDE_PREQ_N: R369.2 ; also on sheet 48 54
XDP_BDE_TDI: R299.2 ; also on sheet 48 54
XDP_BDE_TDO: R677.2 ; also on sheet 48 54
XDP_BDE_TMS: R302.2 ; also on sheet 48 54
XDP_BDE_TRST_N: R301.2 ; also on sheet 48 54
XDP_CPU_OBSDATA_A_MBP2_N: R401.2 ; also on sheet 48 54
XDP_CPU_OBSDATA_A_MBP3_N: R402.2 ; also on sheet 48 54
XDP_CPU_OBSDATA_A_MBP4_N: R388.2 ; also on sheet 48 54
XDP_CPU_OBSDATA_A_MBP5_N: R398.2 ; also on sheet 48 54
XDP_CPU_OBSFN_B_MBP6_N: R767.2 ; also on sheet 48 54
XDP_CPU_OBSFN_B_MBP7_N: R777.2 ; also on sheet 48 54
XDP_CPU_PWR_DEBUG_N: C480.1 R769.1 ; also on sheet 48 54
XDP_CPU_SYSPWROK: C481.1 R772.1 R1172.1 ; also on sheet 47 54 71
XDP_CPU_SYSPWROK_R: R1172.2 ; also on sheet 64
XDP_PCH_TCK0: R148.2 ; also on sheet 48
XDP_PCH_TDI: R140.2 ; also on sheet 48
XDP_PCH_TDO: R528.2 ; also on sheet 48
XDP_PCH_TMS: R155.2 ; also on sheet 48
XDP_PRESENT_N: R340.2 ; also on sheet 48 54

Not connected (* = marked no-connect by the designer): J43 A48* A49* A84* A85* A86* A96* A101* A102* A103* B47* B48* B89* B91* B92* B93* B94* B95* B96* B98* B99* B101* B102* B103*; U90 1(NC)*

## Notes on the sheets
sheet 13
- CMOS CLEAR
- 1
- COM-E_TYPE7_AB_2
sheet 14
- DESIGN NOTE :
  Add Testpoint for CPLD LED for DEBUG.
- CPLD_2
sheet 15
- DDR4 SODIMM CHA_2
sheet 16
- CAD Note:
  C310 Please close to J23.43 Pin
- CPU XDP_2
sheet 17
- BDX-DE GND_2
sheet 18
- DESIGN NOTE : PU FOR DDR4
- BDX-DE MISC, SMBUS
sheet 19
- Need change to NXP and check CRB.
- CHECK THIS. SUPPORT VOLTAGE BEED TO 0.8 to 3.6V
- UART_TXD[1]
- UART_TXD[0]
- 0
- 0
- Design Note
- TAP_NC_SC_STRAP
  1'B1 = PINS ARE USED AS JTAG PORT FOR NC TAP
  1'B0 =GB#_SDP* PINS ARE USED AS FUNCTIONAL PIN OR CAN BE USED FOR SC TAPS THROUGH TAP PROGRAMMING. (DEFAULT)
- BDX-DE UART,MGNT,INT,SVID_2
